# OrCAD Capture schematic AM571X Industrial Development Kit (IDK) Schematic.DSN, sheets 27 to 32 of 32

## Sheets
27 Pg16: Gbit Ethernet #0: size C
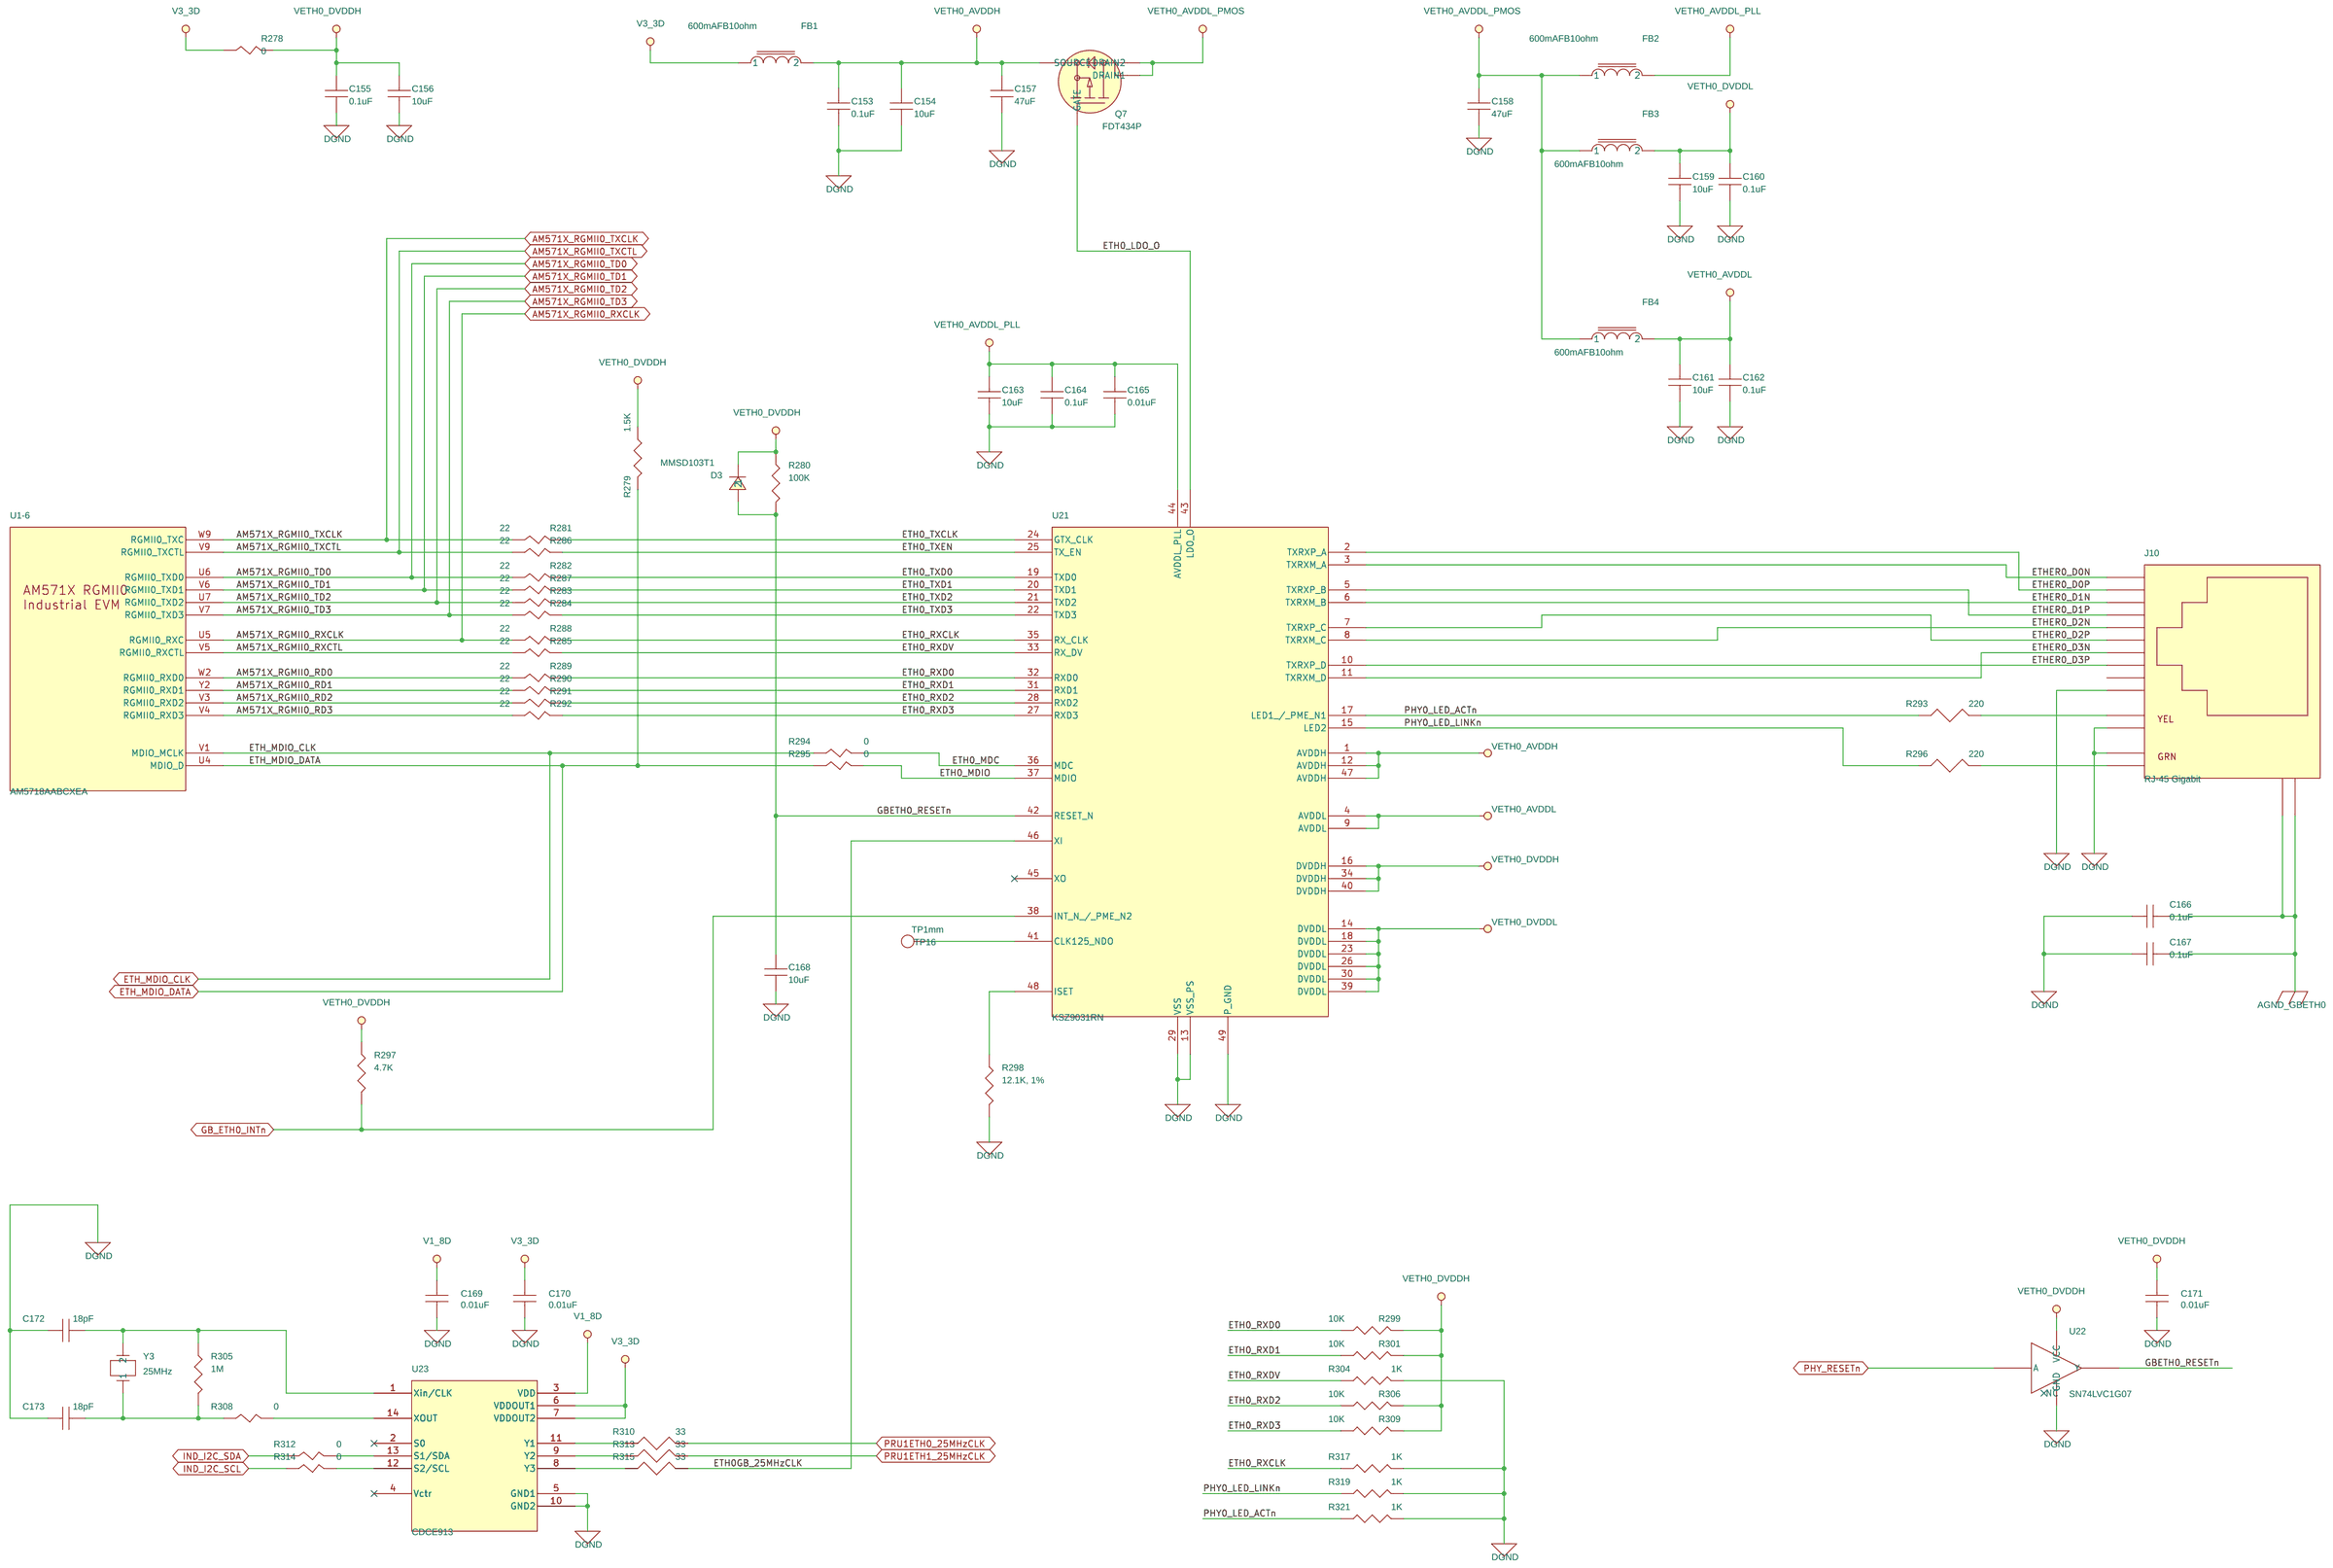
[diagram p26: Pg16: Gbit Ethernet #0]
28 Pg07: QSPI Flash Memory: size C
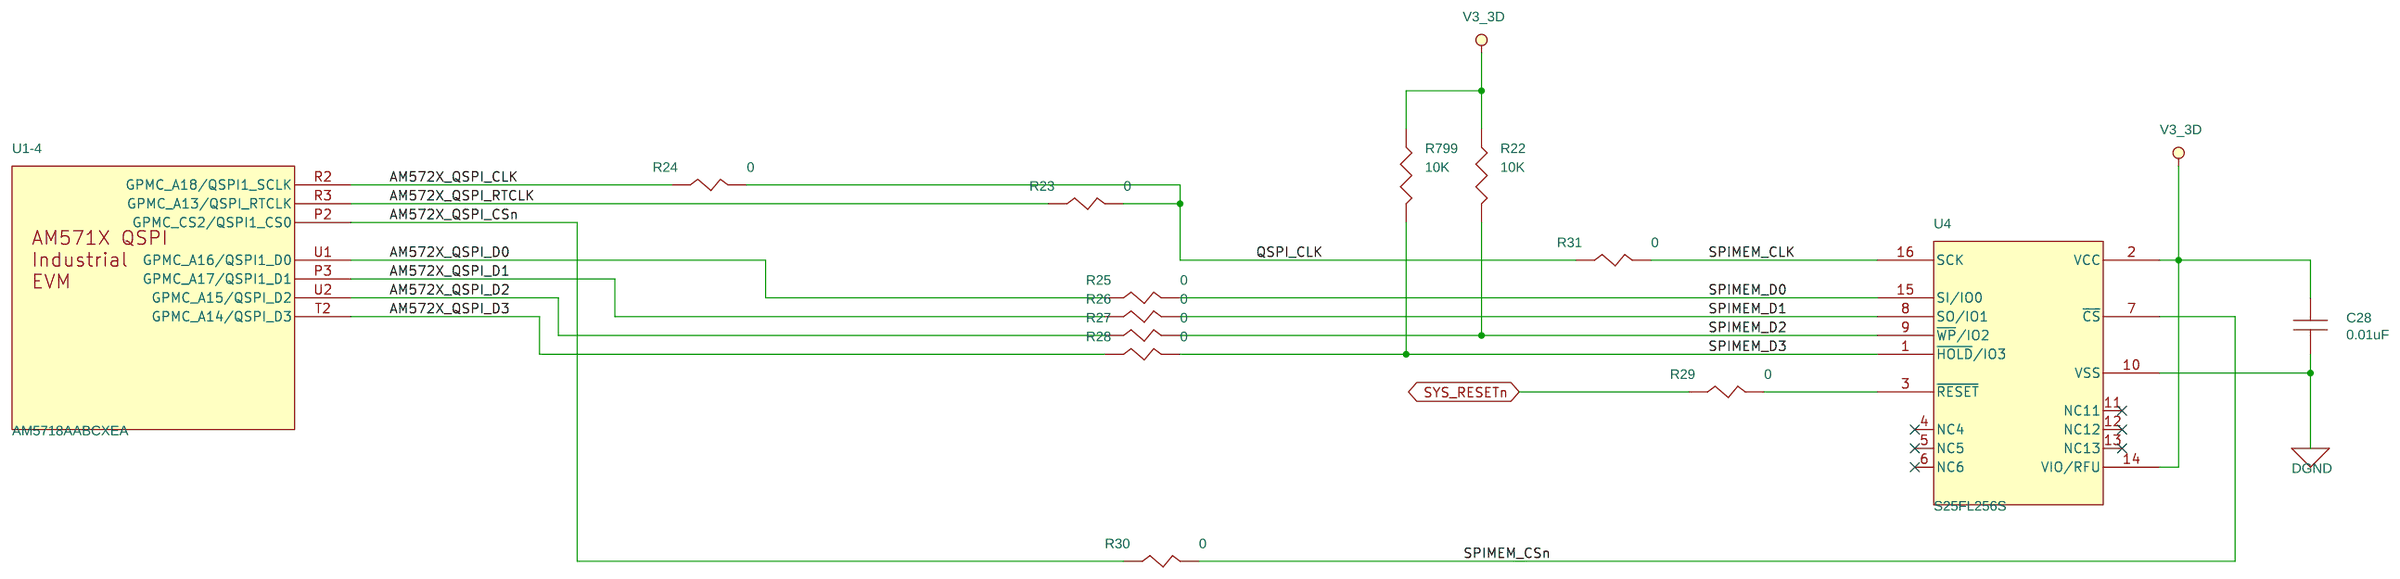
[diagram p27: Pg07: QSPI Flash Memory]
29 Pg32: Expansion Connector: size C
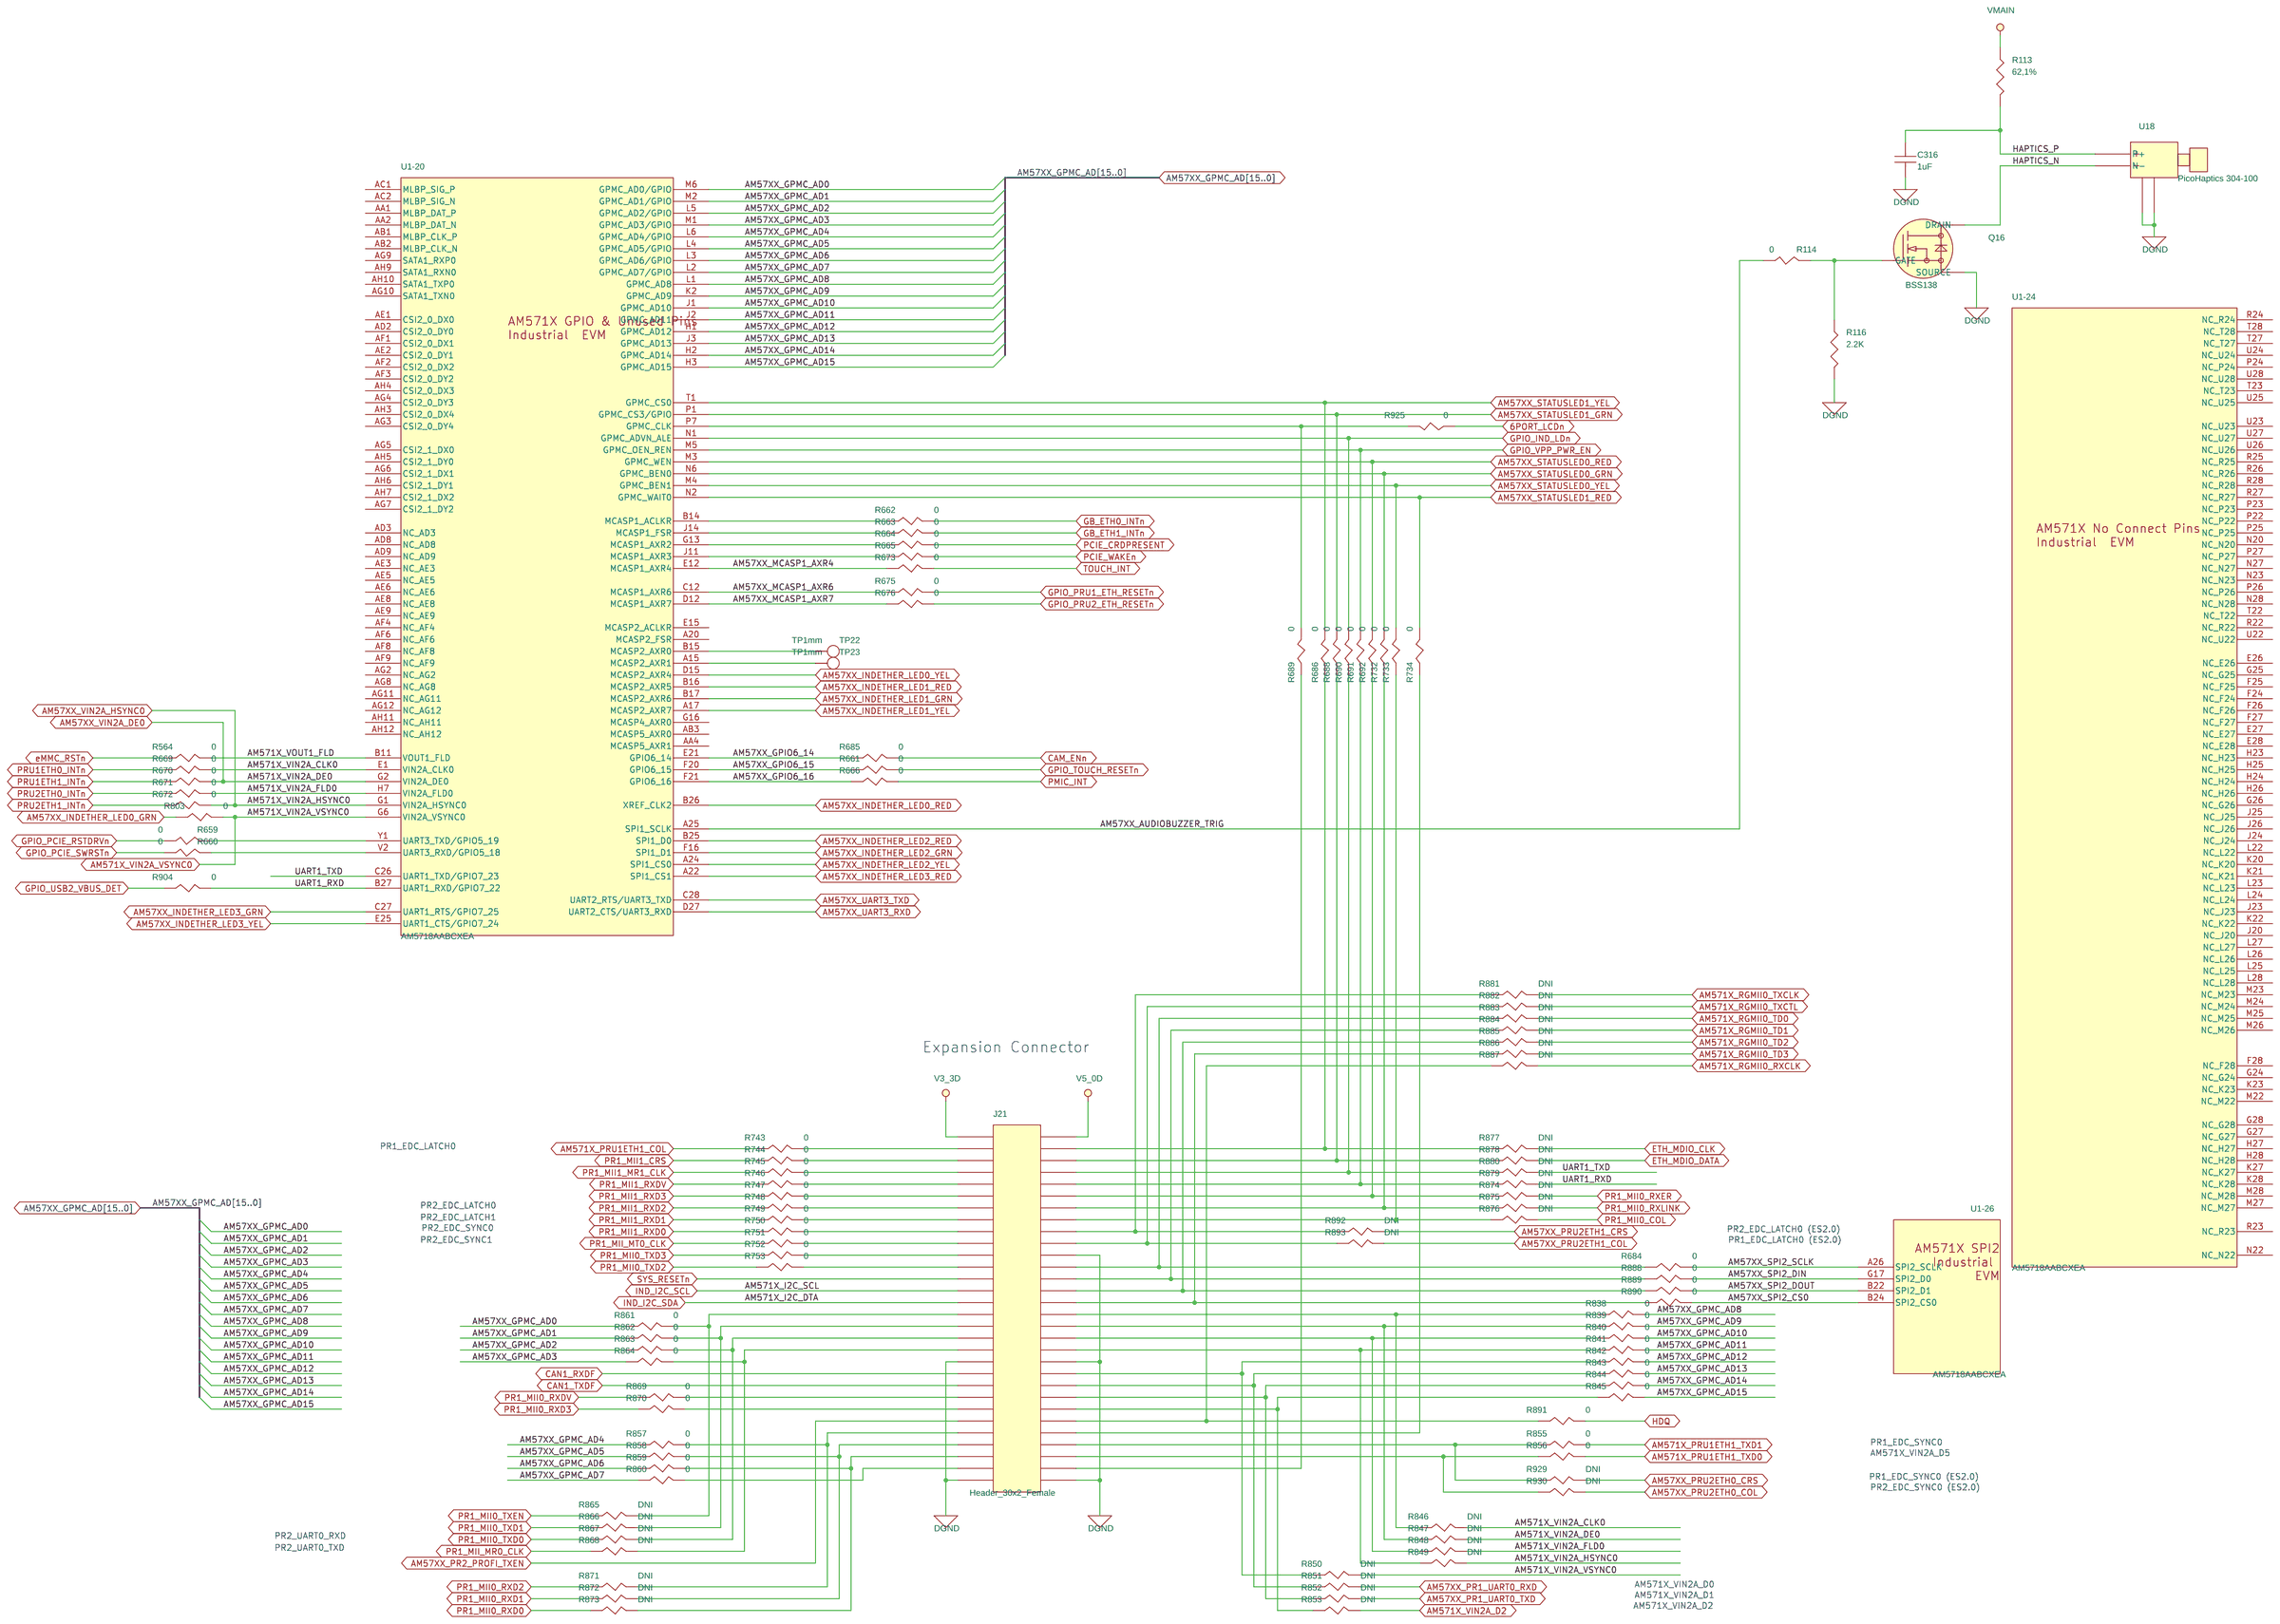
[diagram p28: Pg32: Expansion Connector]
30 Pg02: Processor subsystem: size C
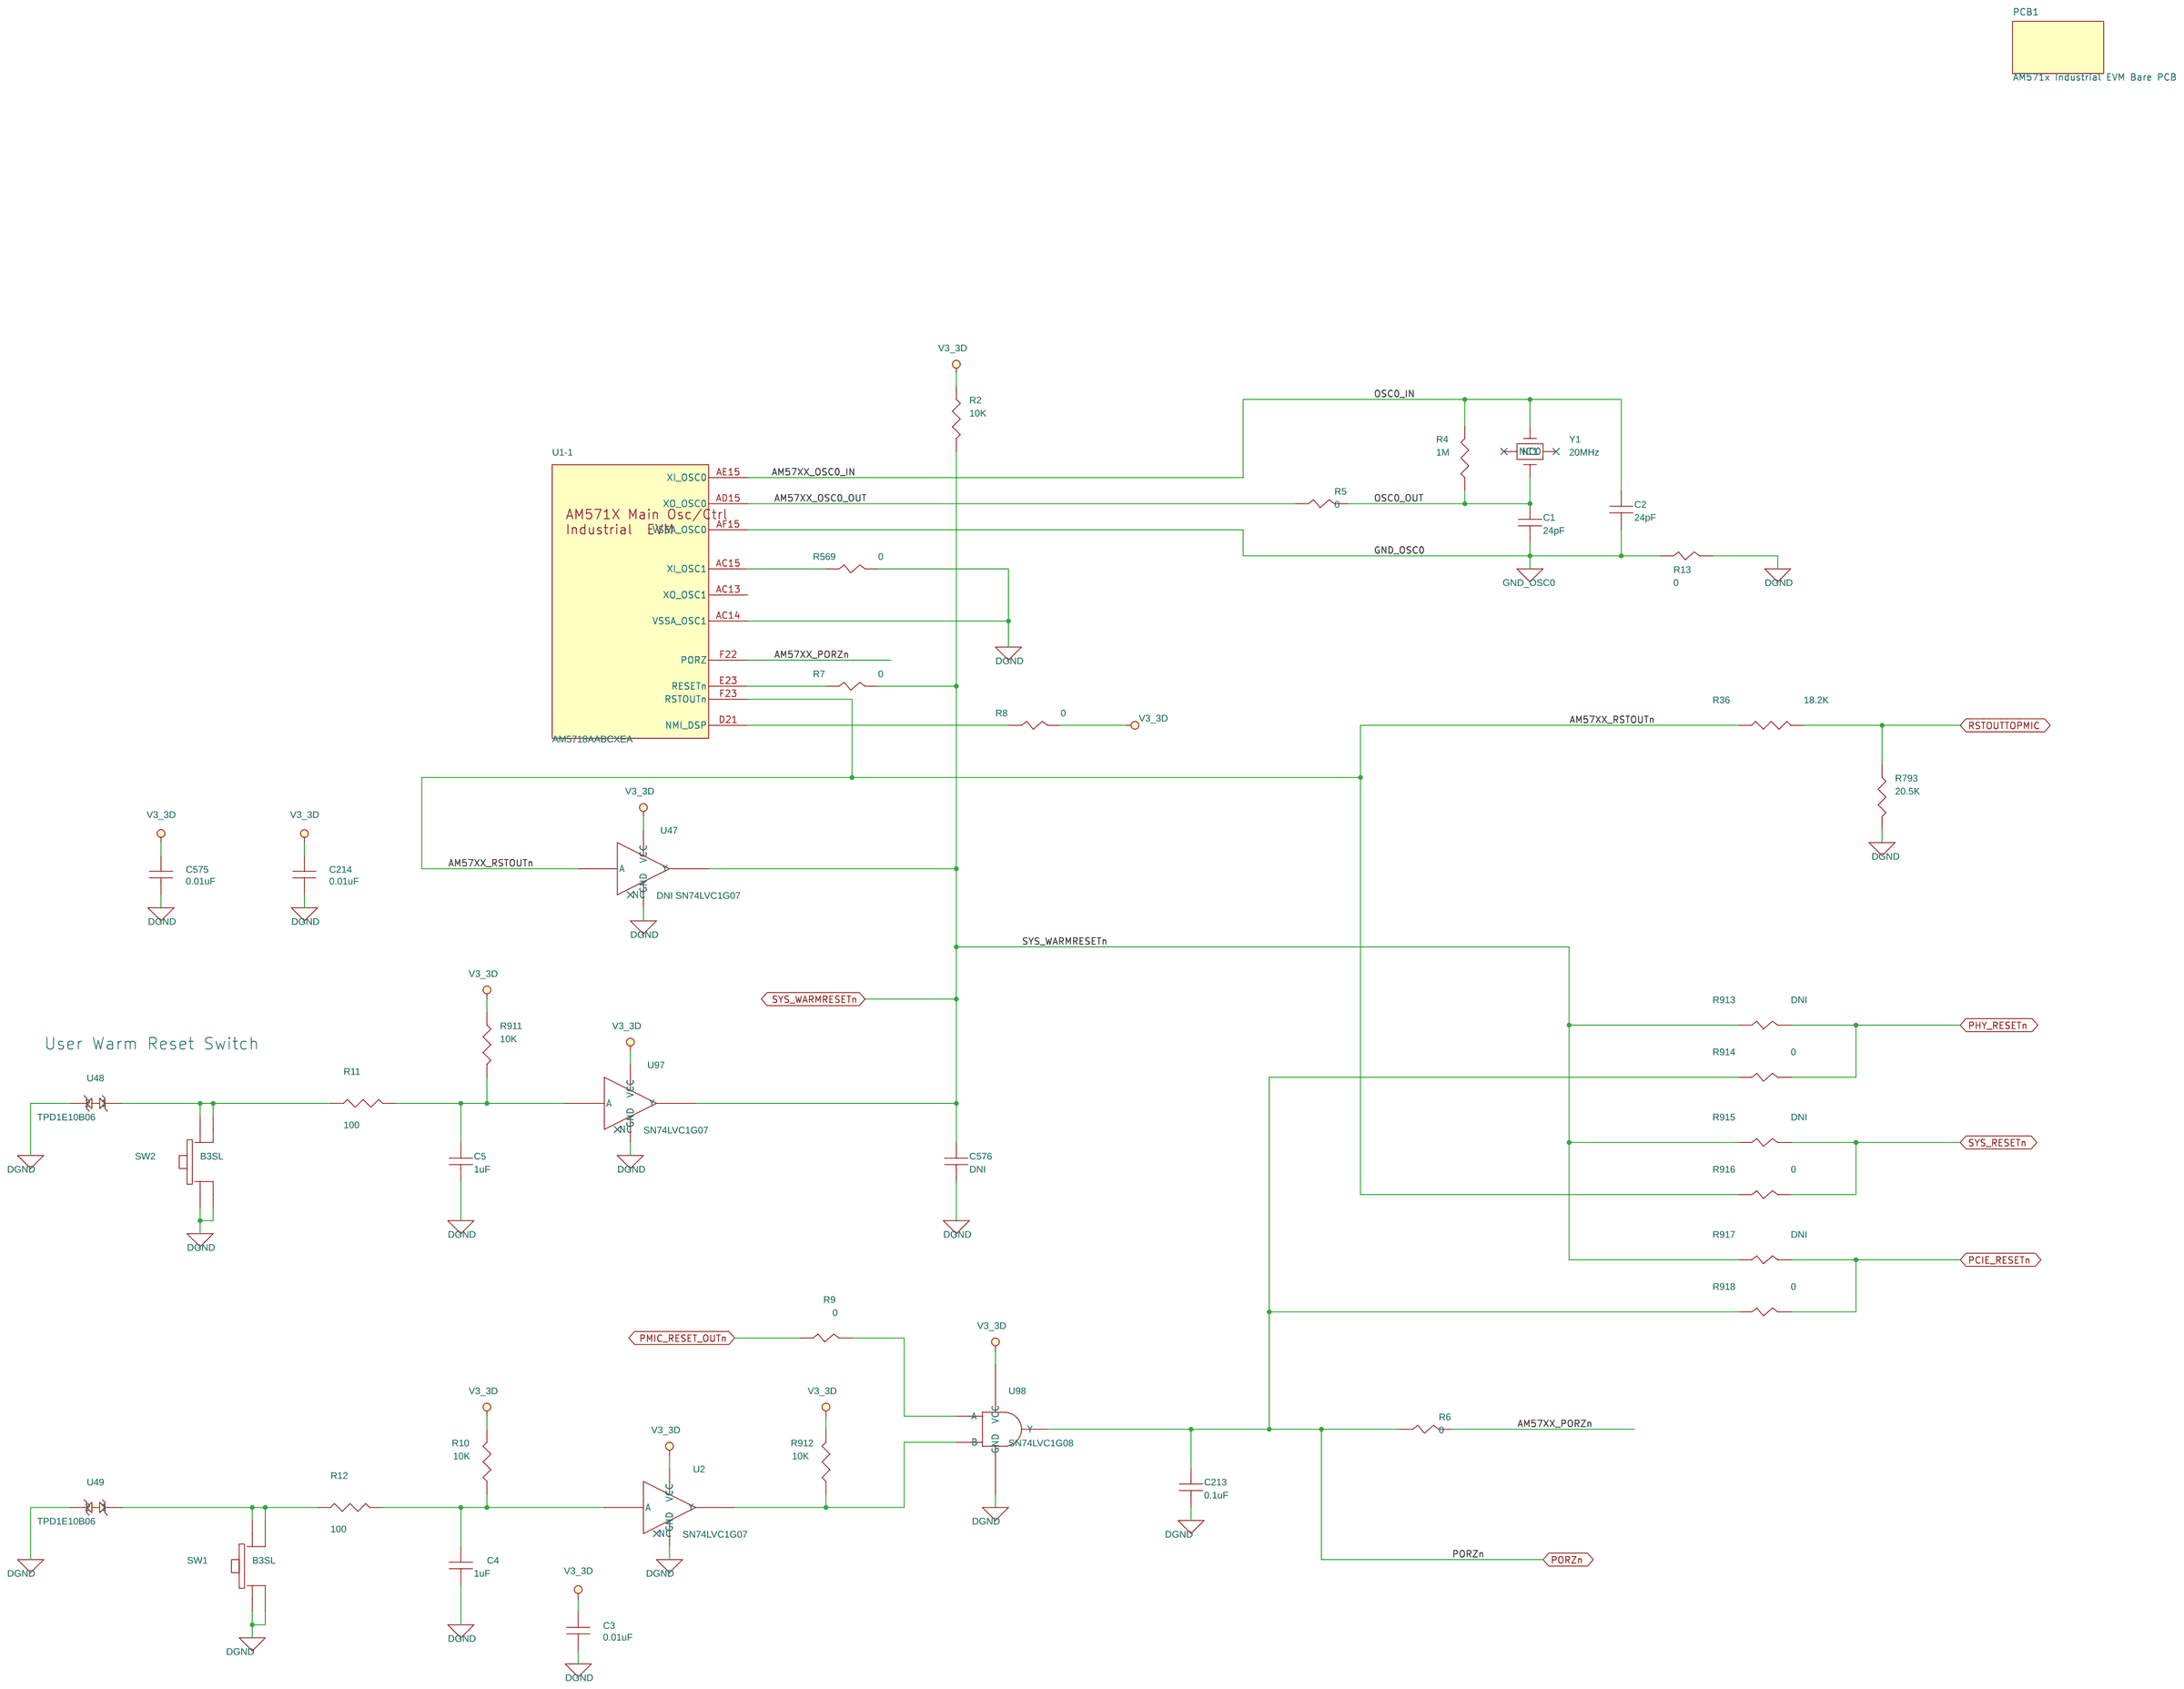
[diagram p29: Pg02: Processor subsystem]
31 Pg04: Processor Pwr Decoupling: size C
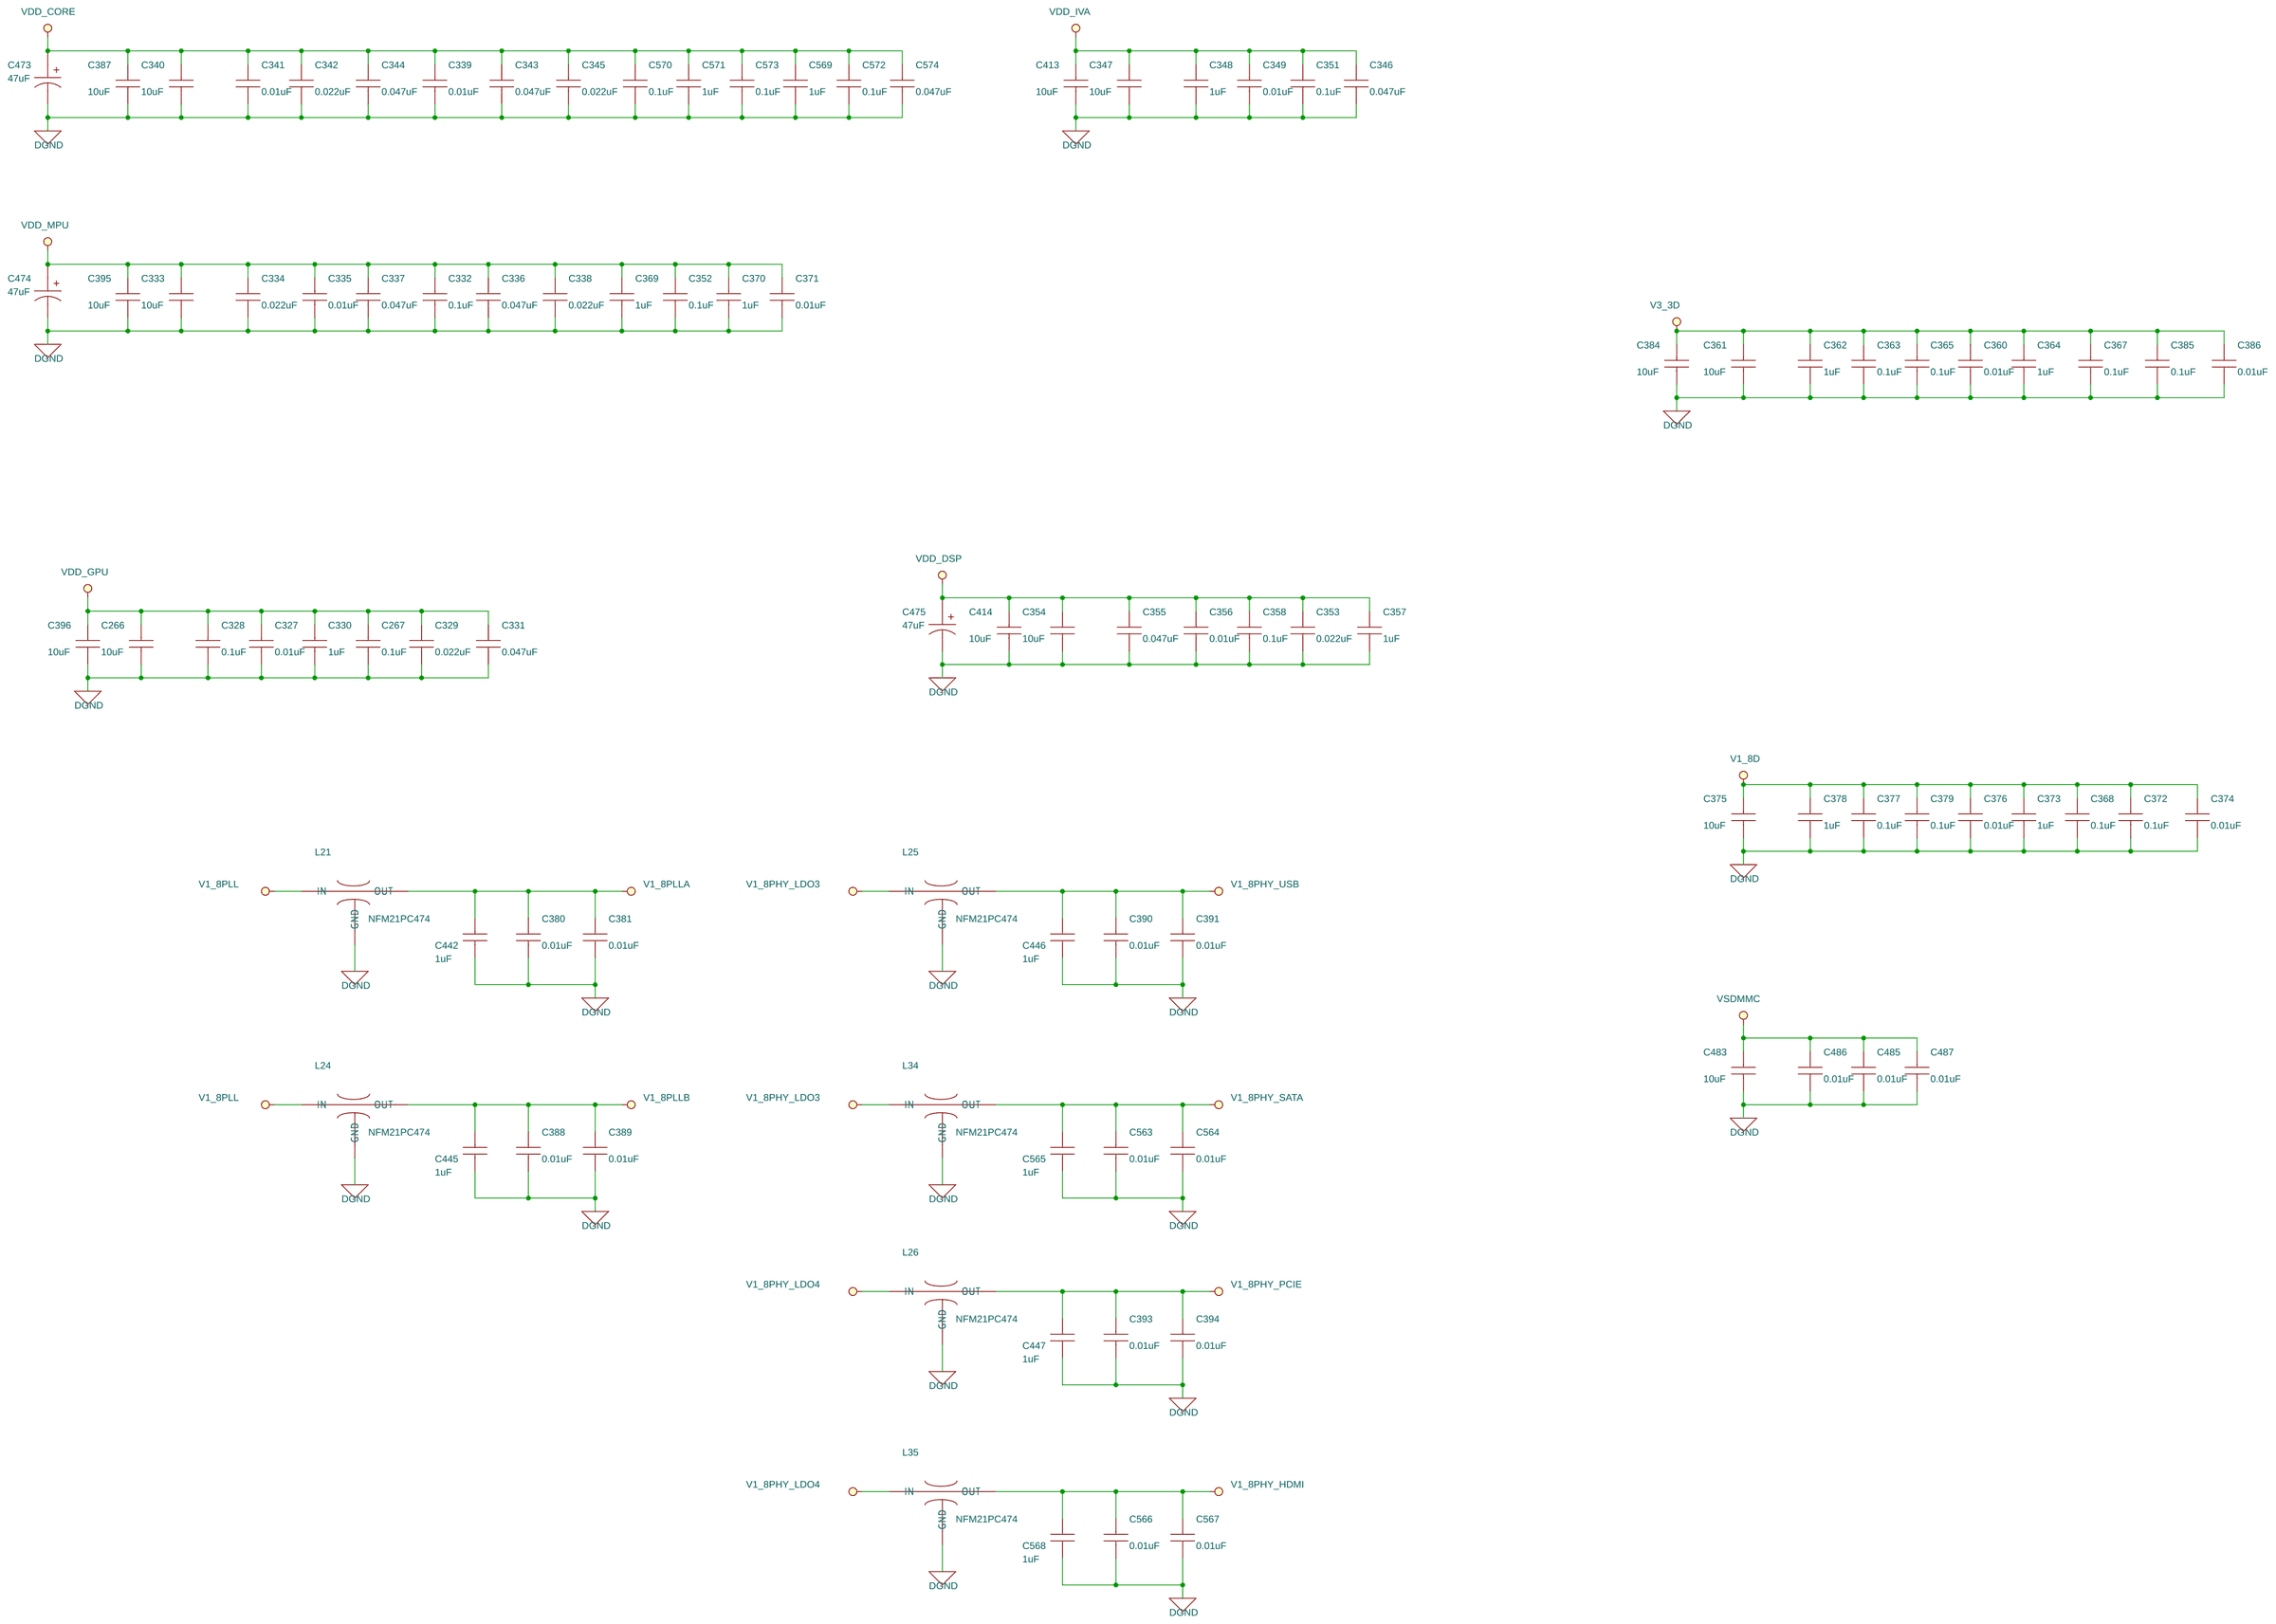
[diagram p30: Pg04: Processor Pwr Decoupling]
32 Pg14: Ind Ethrnt & Status LED's: size C
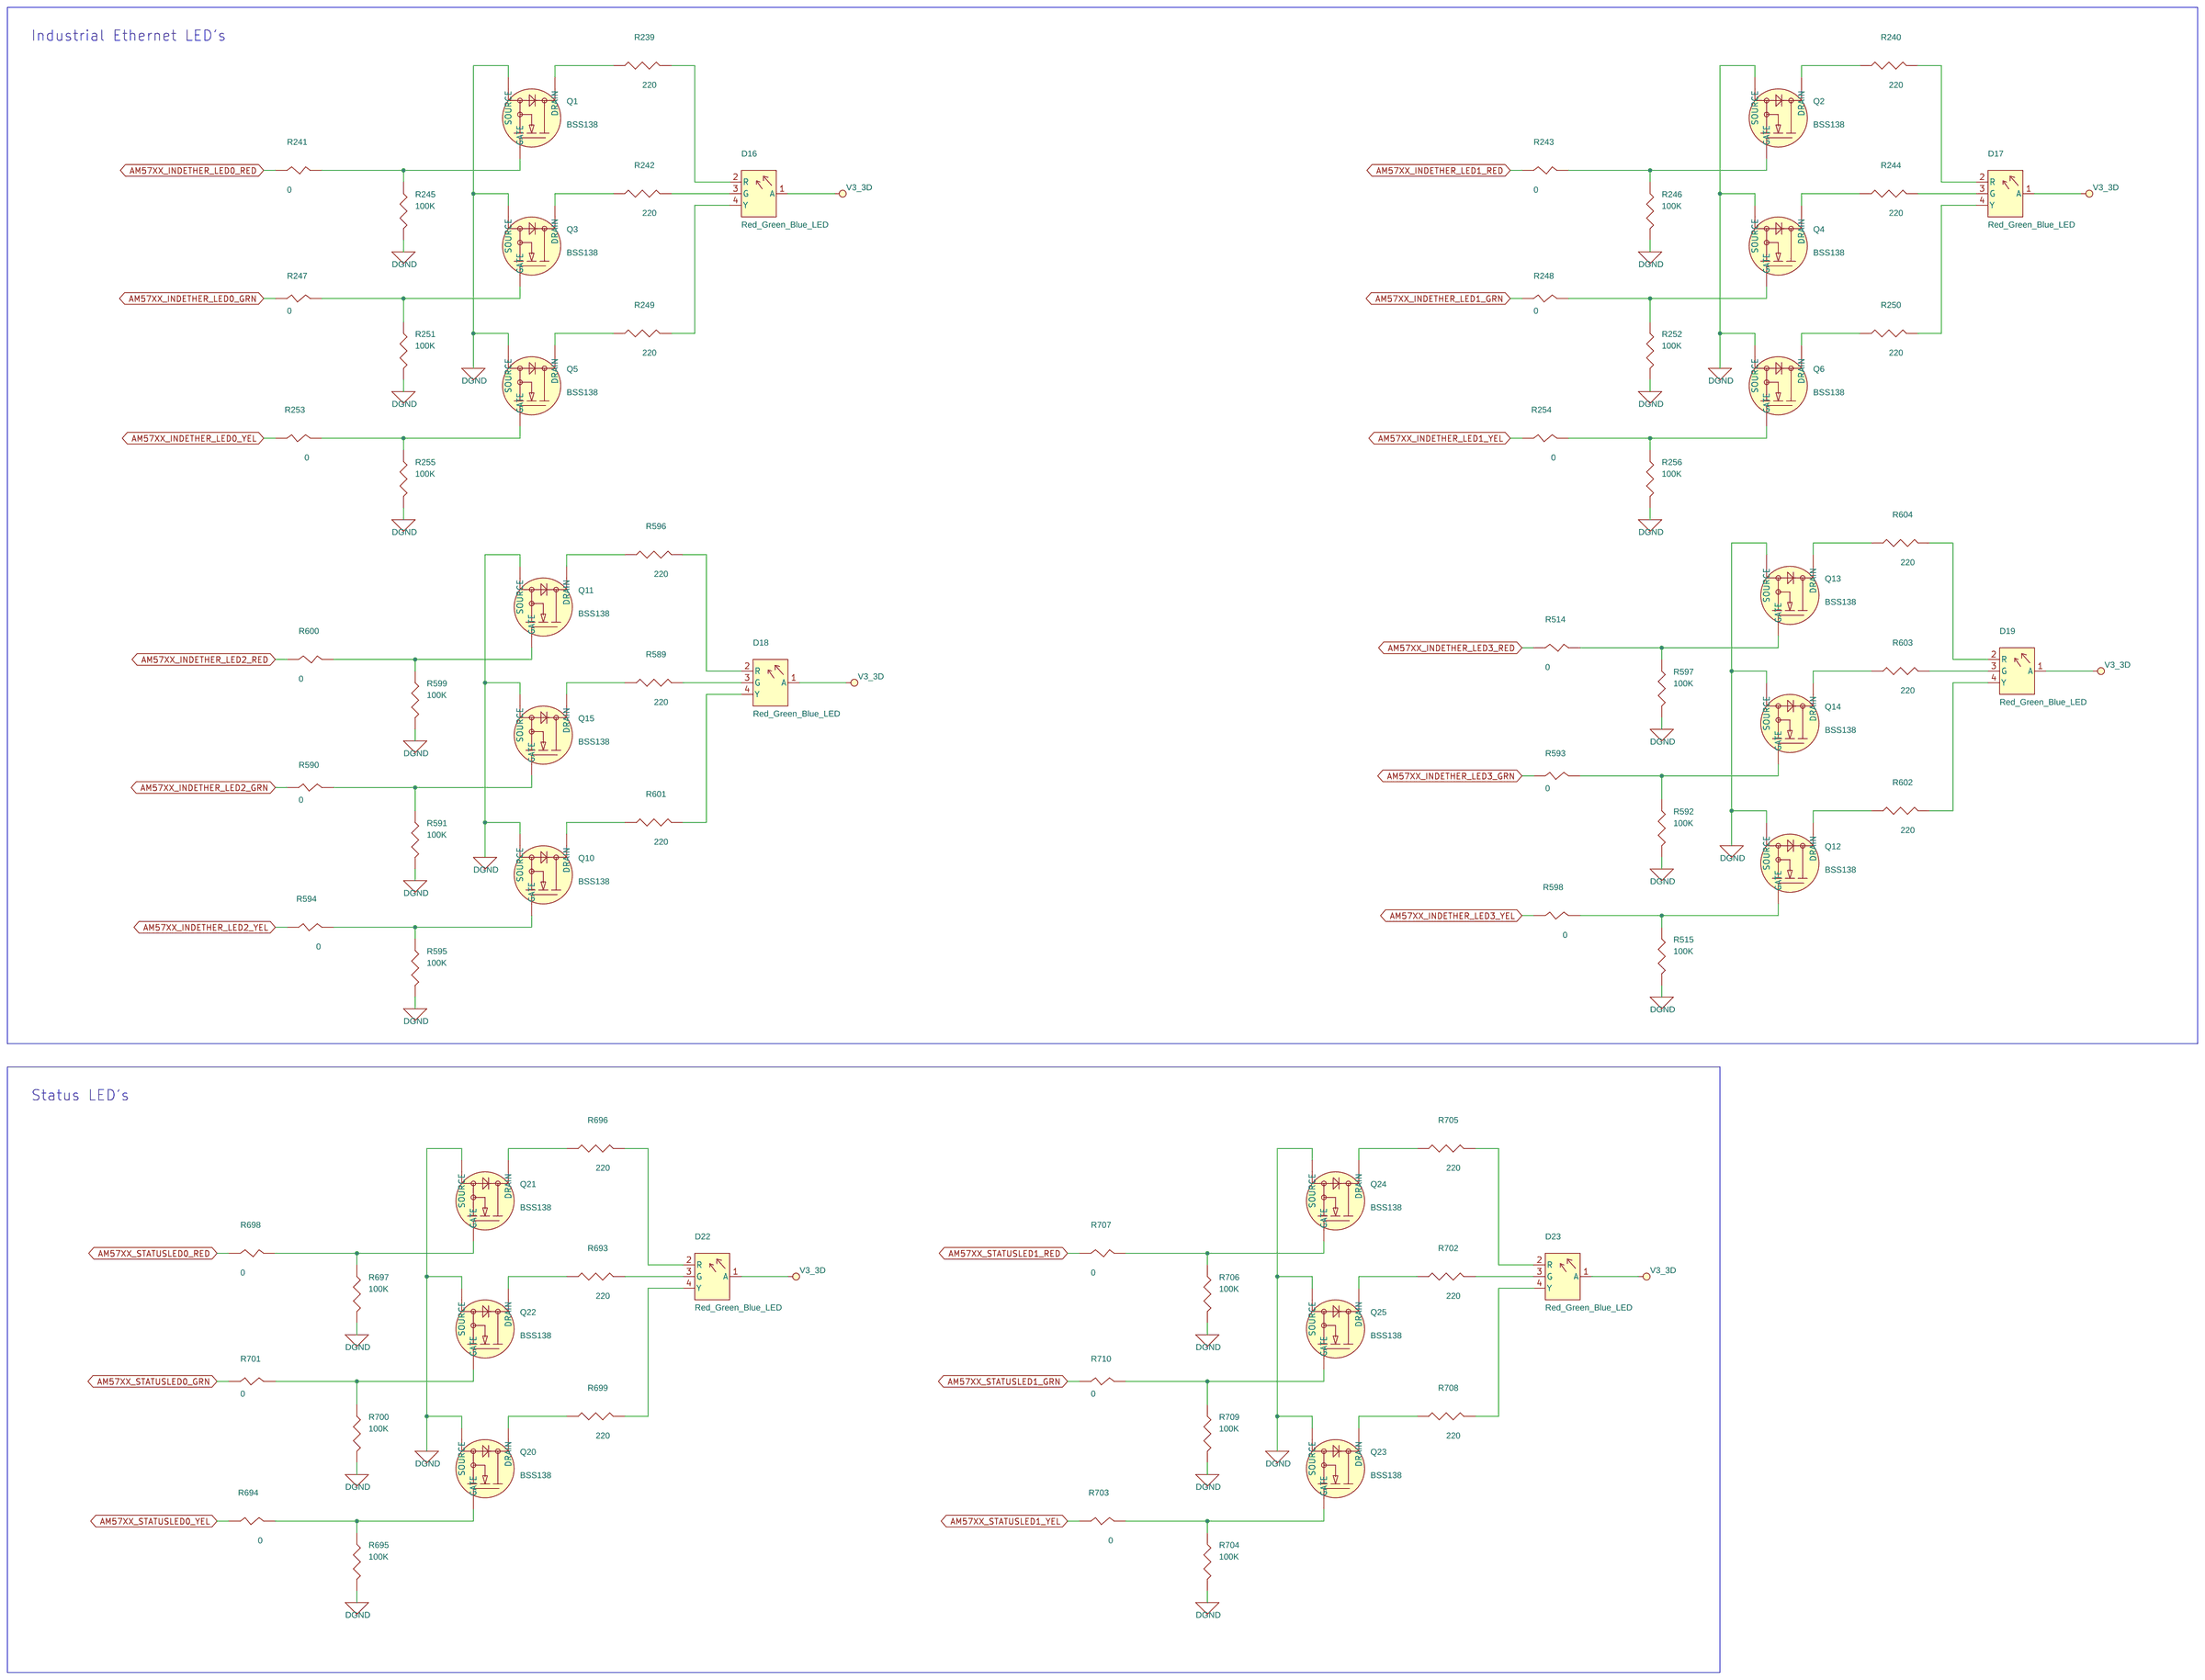
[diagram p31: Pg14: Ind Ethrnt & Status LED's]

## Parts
sheet Pg02: Processor subsystem
C1  24pF  [SM-7351-CAP-0402]
C2  24pF  [SM-7351-CAP-0402]
C3  0.01uF  [SM-7351-CAP-0402]
C4  1uF  [SM-7351-CAP-0402]
C5  1uF  [SM-7351-CAP-0402]
C213  0.1uF  [SM-7351-CAP-0402]
C214  0.01uF  [SM-7351-CAP-0402]
C575  0.01uF  [SM-7351-CAP-0402]
C576  DNI  [SM-7351-CAP-0402]
PCB1  AM571x Industrial EVM Bare PCB  [DNP]
R2  10K  [SM-7351-RES-0402]
R4  1M  [SM-7351-RES-0402]
R5  0  [SM-7351-RES-0402]
R6  0  [SM-7351-RES-0402]
R7  0  [SM-7351-RES-0402]
R8  0  [SM-7351-RES-0402]
R9  0  [SM-7351-RES-0402]
R10  10K  [SM-7351-RES-0402]
R11  100  [SM-7351-RES-0402]
R12  100  [SM-7351-RES-0402]
R13  0  [SM-7351-RES-0402]
R36  18.2K  [SM-7351-RES-0402]
R569  0  [SM-7351-RES-0402]
R793  20.5K  [SM-7351-RES-0402]
R911  10K  [SM-7351-RES-0402]
R912  10K  [SM-7351-RES-0402]
R913  DNI  [SM-7351-RES-0402]
R914  0  [SM-7351-RES-0402]
R915  DNI  [SM-7351-RES-0402]
R916  0  [SM-7351-RES-0402]
R917  DNI  [SM-7351-RES-0402]
R918  0  [SM-7351-RES-0402]
SW1  B3SL  [SW_B3SL-1022P]
SW2  B3SL  [SW_B3SL-1022P]
U2  SN74LVC1G07  [SC70-5-43M]
U47  DNI SN74LVC1G07  [SC70-5-43M]
U48  TPD1E10B06  [tpd1e10b06-2l]
U49  TPD1E10B06  [tpd1e10b06-2l]
U97  SN74LVC1G07  [SC70-5-43M]
U98  SN74LVC1G08  [sm-so-sc70-5]
Y1  20MHz  [XTAL2X3-30M]
sheet Pg04: Processor Pwr Decoupling
C266  10uF  [SM-7351-CAP-0805]
C267  0.1uF  [SM-7351-CAP-0402]
C327  0.01uF  [SM-7351-CAP-0402]
C328  0.1uF  [SM-7351-CAP-0402]
C329  0.022uF  [SM-7351-CAP-0402]
C330  1uF  [SM-7351-CAP-0402]
C331  0.047uF  [SM-7351-CAP-0402]
C332  0.1uF  [SM-7351-CAP-0402]
C333  10uF  [SM-7351-CAP-0805]
C334  0.022uF  [SM-7351-CAP-0402]
C335  0.01uF  [SM-7351-CAP-0402]
C336  0.047uF  [SM-7351-CAP-0402]
C337  0.047uF  [SM-7351-CAP-0402]
C338  0.022uF  [SM-7351-CAP-0402]
C339  0.01uF  [SM-7351-CAP-0402]
C340  10uF  [SM-7351-CAP-0805]
C341  0.01uF  [SM-7351-CAP-0402]
C342  0.022uF  [SM-7351-CAP-0402]
C343  0.047uF  [SM-7351-CAP-0402]
C344  0.047uF  [SM-7351-CAP-0402]
C345  0.022uF  [SM-7351-CAP-0402]
C346  0.047uF  [SM-7351-CAP-0402]
C347  10uF  [SM-7351-CAP-0805]
C348  1uF  [SM-7351-CAP-0402]
C349  0.01uF  [SM-7351-CAP-0402]
C351  0.1uF  [SM-7351-CAP-0402]
C352  0.1uF  [SM-7351-CAP-0402]
C353  0.022uF  [SM-7351-CAP-0402]
C354  10uF  [SM-7351-CAP-0805]
C355  0.047uF  [SM-7351-CAP-0402]
C356  0.01uF  [SM-7351-CAP-0402]
C357  1uF  [SM-7351-CAP-0402]
C358  0.1uF  [SM-7351-CAP-0402]
C360  0.01uF  [SM-7351-CAP-0402]
C361  10uF  [SM-7351-CAP-0805]
C362  1uF  [SM-7351-CAP-0402]
C363  0.1uF  [SM-7351-CAP-0402]
C364  1uF  [SM-7351-CAP-0402]
C365  0.1uF  [SM-7351-CAP-0402]
C367  0.1uF  [SM-7351-CAP-0402]
C368  0.1uF  [SM-7351-CAP-0402]
C369  1uF  [SM-7351-CAP-0402]
C370  1uF  [SM-7351-CAP-0402]
C371  0.01uF  [SM-7351-CAP-0402]
C372  0.1uF  [SM-7351-CAP-0402]
C373  1uF  [SM-7351-CAP-0402]
C374  0.01uF  [SM-7351-CAP-0402]
C375  10uF  [SM-7351-CAP-0805]
C376  0.01uF  [SM-7351-CAP-0402]
C377  0.1uF  [SM-7351-CAP-0402]
C378  1uF  [SM-7351-CAP-0402]
C379  0.1uF  [SM-7351-CAP-0402]
C380  0.01uF  [SM-7351-CAP-0402]
C381  0.01uF  [SM-7351-CAP-0402]
C384  10uF  [SM-7351-CAP-0805]
C385  0.1uF  [SM-7351-CAP-0402]
C386  0.01uF  [SM-7351-CAP-0402]
C387  10uF  [SM-7351-CAP-0805]
C388  0.01uF  [SM-7351-CAP-0402]
C389  0.01uF  [SM-7351-CAP-0402]
C390  0.01uF  [SM-7351-CAP-0402]
C391  0.01uF  [SM-7351-CAP-0402]
C393  0.01uF  [SM-7351-CAP-0402]
C394  0.01uF  [SM-7351-CAP-0402]
C395  10uF  [SM-7351-CAP-0805]
C396  10uF  [SM-7351-CAP-0805]
C413  10uF  [SM-7351-CAP-0805]
C414  10uF  [SM-7351-CAP-0805]
C442  1uF  [SM-7351-CAP-0402]
C445  1uF  [SM-7351-CAP-0402]
C446  1uF  [SM-7351-CAP-0402]
C447  1uF  [SM-7351-CAP-0402]
C473  47uF  [7343]
C474  47uF  [7343]
C475  47uF  [7343]
C483  10uF  [SM-7351-CAP-0805]
C485  0.01uF  [SM-7351-CAP-0402]
C486  0.01uF  [SM-7351-CAP-0402]
C487  0.01uF  [SM-7351-CAP-0402]
C563  0.01uF  [SM-7351-CAP-0402]
C564  0.01uF  [SM-7351-CAP-0402]
C565  1uF  [SM-7351-CAP-0402]
C566  0.01uF  [SM-7351-CAP-0402]
C567  0.01uF  [SM-7351-CAP-0402]
C568  1uF  [SM-7351-CAP-0402]
C569  1uF  [SM-7351-CAP-0402]
C570  0.1uF  [SM-7351-CAP-0402]
C571  1uF  [SM-7351-CAP-0402]
C572  0.1uF  [SM-7351-CAP-0402]
C573  0.1uF  [SM-7351-CAP-0402]
C574  0.047uF  [SM-7351-CAP-0402]
L21  NFM21PC474  [FILT-NFM21PC]
L24  NFM21PC474  [FILT-NFM21PC]
L25  NFM21PC474  [FILT-NFM21PC]
L26  NFM21PC474  [FILT-NFM21PC]
L34  NFM21PC474  [FILT-NFM21PC]
L35  NFM21PC474  [FILT-NFM21PC]
sheet Pg07: QSPI Flash Memory
C28  0.01uF  [SM-7351-CAP-0402]
R22  10K  [SM-7351-RES-0402]
R23  0  [SM-7351-RES-0402]
R24  0  [SM-7351-RES-0402]
R25  0  [SM-7351-RES-0402]
R26  0  [SM-7351-RES-0402]
R27  0  [SM-7351-RES-0402]
R28  0  [SM-7351-RES-0402]
R29  0  [SM-7351-RES-0402]
R30  0  [SM-7351-RES-0402]
R31  0  [SM-7351-RES-0402]
R799  10K  [SM-7351-RES-0402]
U4  S25FL256S  [soic_16pin_dw]
sheet Pg14: Ind Ethrnt & Status LED's
D16  Red_Green_Blue_LED  [LED-SM1210]
D17  Red_Green_Blue_LED  [LED-SM1210]
D18  Red_Green_Blue_LED  [LED-SM1210]
D19  Red_Green_Blue_LED  [LED-SM1210]
D22  Red_Green_Blue_LED  [LED-SM1210]
D23  Red_Green_Blue_LED  [LED-SM1210]
Q1  BSS138  [SOT23-3]
Q2  BSS138  [SOT23-3]
Q3  BSS138  [SOT23-3]
Q4  BSS138  [SOT23-3]
Q5  BSS138  [SOT23-3]
Q6  BSS138  [SOT23-3]
Q10  BSS138  [SOT23-3]
Q11  BSS138  [SOT23-3]
Q12  BSS138  [SOT23-3]
Q13  BSS138  [SOT23-3]
Q14  BSS138  [SOT23-3]
Q15  BSS138  [SOT23-3]
Q20  BSS138  [SOT23-3]
Q21  BSS138  [SOT23-3]
Q22  BSS138  [SOT23-3]
Q23  BSS138  [SOT23-3]
Q24  BSS138  [SOT23-3]
Q25  BSS138  [SOT23-3]
R239  220  [SM-7351-RES-0402]
R240  220  [SM-7351-RES-0402]
R241  0  [SM-7351-RES-0402]
R242  220  [SM-7351-RES-0402]
R243  0  [SM-7351-RES-0402]
R244  220  [SM-7351-RES-0402]
R245  100K  [SM-7351-RES-0402]
R246  100K  [SM-7351-RES-0402]
R247  0  [SM-7351-RES-0402]
R248  0  [SM-7351-RES-0402]
R249  220  [SM-7351-RES-0402]
R250  220  [SM-7351-RES-0402]
R251  100K  [SM-7351-RES-0402]
R252  100K  [SM-7351-RES-0402]
R253  0  [SM-7351-RES-0402]
R254  0  [SM-7351-RES-0402]
R255  100K  [SM-7351-RES-0402]
R256  100K  [SM-7351-RES-0402]
R514  0  [SM-7351-RES-0402]
R515  100K  [SM-7351-RES-0402]
R589  220  [SM-7351-RES-0402]
R590  0  [SM-7351-RES-0402]
R591  100K  [SM-7351-RES-0402]
R592  100K  [SM-7351-RES-0402]
R593  0  [SM-7351-RES-0402]
R594  0  [SM-7351-RES-0402]
R595  100K  [SM-7351-RES-0402]
R596  220  [SM-7351-RES-0402]
R597  100K  [SM-7351-RES-0402]
R598  0  [SM-7351-RES-0402]
R599  100K  [SM-7351-RES-0402]
R600  0  [SM-7351-RES-0402]
R601  220  [SM-7351-RES-0402]
R602  220  [SM-7351-RES-0402]
R603  220  [SM-7351-RES-0402]
R604  220  [SM-7351-RES-0402]
R693  220  [SM-7351-RES-0402]
R694  0  [SM-7351-RES-0402]
R695  100K  [SM-7351-RES-0402]
R696  220  [SM-7351-RES-0402]
R697  100K  [SM-7351-RES-0402]
R698  0  [SM-7351-RES-0402]
R699  220  [SM-7351-RES-0402]
R700  100K  [SM-7351-RES-0402]
R701  0  [SM-7351-RES-0402]
R702  220  [SM-7351-RES-0402]
R703  0  [SM-7351-RES-0402]
R704  100K  [SM-7351-RES-0402]
R705  220  [SM-7351-RES-0402]
R706  100K  [SM-7351-RES-0402]
R707  0  [SM-7351-RES-0402]
R708  220  [SM-7351-RES-0402]
R709  100K  [SM-7351-RES-0402]
R710  0  [SM-7351-RES-0402]
sheet Pg16: Gbit Ethernet #0
C153  0.1uF  [SM-7351-CAP-0402]
C154  10uF  [SM-7351-CAP-0805]
C155  0.1uF  [SM-7351-CAP-0402]
C156  10uF  [SM-7351-CAP-0805]
C157  47uF  [SM-7351-CAP-1206]
C158  47uF  [SM-7351-CAP-1206]
C159  10uF  [SM-7351-CAP-0805]
C160  0.1uF  [SM-7351-CAP-0402]
C161  10uF  [SM-7351-CAP-0805]
C162  0.1uF  [SM-7351-CAP-0402]
C163  10uF  [SM-7351-CAP-0805]
C164  0.1uF  [SM-7351-CAP-0402]
C165  0.01uF  [SM-7351-CAP-0402]
C166  0.1uF  [SM-7351-CAP-0402]
C167  0.1uF  [SM-7351-CAP-0402]
C168  10uF  [SM-7351-CAP-0805]
C169  0.01uF  [SM-7351-CAP-0402]
C170  0.01uF  [SM-7351-CAP-0402]
C171  0.01uF  [SM-7351-CAP-0402]
C172  18pF  [SM-7351-CAP-0402]
C173  18pF  [SM-7351-CAP-0402]
D3  MMSD103T1  [sod-123]
FB1  600mAFB10ohm  [HF70ACB201209]
FB2  600mAFB10ohm  [HF70ACB201209]
FB3  600mAFB10ohm  [HF70ACB201209]
FB4  600mAFB10ohm  [HF70ACB201209]
J10  RJ-45 Gigabit  [CNRJ45-1X1WLED-598M]
Q7  FDT434P  [SOT223-4]
R278  0  [SM-7351-RES-0603]
R279  1.5K  [SM-7351-RES-0402]
R280  100K  [SM-7351-RES-0402]
R281  22  [SM-7351-RES-0402]
R282  22  [SM-7351-RES-0402]
R283  22  [SM-7351-RES-0402]
R284  22  [SM-7351-RES-0402]
R285  22  [SM-7351-RES-0402]
R286  22  [SM-7351-RES-0402]
R287  22  [SM-7351-RES-0402]
R288  22  [SM-7351-RES-0402]
R289  22  [SM-7351-RES-0402]
R290  22  [SM-7351-RES-0402]
R291  22  [SM-7351-RES-0402]
R292  22  [SM-7351-RES-0402]
R293  220  [SM-7351-RES-0402]
R294  0  [SM-7351-RES-0402]
R295  0  [SM-7351-RES-0402]
R296  220  [SM-7351-RES-0402]
R297  4.7K  [SM-7351-RES-0402]
R298  12.1K, 1%  [SM-7351-RES-0402]
R299  10K  [SM-7351-RES-0402]
R301  10K  [SM-7351-RES-0402]
R304  1K  [SM-7351-RES-0402]
R305  1M  [SM-7351-RES-0402]
R306  10K  [SM-7351-RES-0402]
R308  0  [SM-7351-RES-0402]
R309  10K  [SM-7351-RES-0402]
R310  33  [SM-7351-RES-0402]
R312  0  [SM-7351-RES-0402]
R313  33  [SM-7351-RES-0402]
R314  0  [SM-7351-RES-0402]
R315  33  [SM-7351-RES-0402]
R317  1K  [SM-7351-RES-0402]
R319  1K  [SM-7351-RES-0402]
R321  1K  [SM-7351-RES-0402]
TP16  TP1mm  [tp_smd1mmcircle]
U21  KSZ9031RN  [qfn7x7-48]
U22  SN74LVC1G07  [SC70-5-43M]
U23  CDCE913  [TSSOP5X4-14-47M]
Y3  25MHz  [SM_OSC_ABM3]
sheet Pg32: Expansion Connector
C316  1uF  [SM-7351-CAP-0603]
J21  Header_30x2_Female  [HDR2X30-2mm-177m]
Q16  BSS138  [SOT23-3]
R113  62,1%  [sm-7351-res-0402]
R114  0  [SM-7351-RES-0402]
R116  2.2K  [sm-7351-res-0402]
R564  0  [SM-7351-RES-0402]
R659  0  [SM-7351-RES-0402]
R660  0  [SM-7351-RES-0402]
R661  0  [SM-7351-RES-0402]
R662  0  [SM-7351-RES-0402]
R663  0  [SM-7351-RES-0402]
R664  0  [SM-7351-RES-0402]
R665  0  [SM-7351-RES-0402]
R666  0  [SM-7351-RES-0402]
R669  0  [SM-7351-RES-0402]
R670  0  [SM-7351-RES-0402]
R671  0  [SM-7351-RES-0402]
R672  0  [SM-7351-RES-0402]
R673  0  [SM-7351-RES-0402]
R675  0  [SM-7351-RES-0402]
R676  0  [SM-7351-RES-0402]
R684  0  [SM-7351-RES-0402]
R685  0  [SM-7351-RES-0402]
R686  0  [SM-7351-RES-0402]
R688  0  [SM-7351-RES-0402]
R689  0  [SM-7351-RES-0402]
R690  0  [SM-7351-RES-0402]
R691  0  [SM-7351-RES-0402]
R692  0  [SM-7351-RES-0402]
R732  0  [SM-7351-RES-0402]
R733  0  [SM-7351-RES-0402]
R734  0  [SM-7351-RES-0402]
R743  0  [SM-7351-RES-0402]
R744  0  [SM-7351-RES-0402]
R745  0  [SM-7351-RES-0402]
R746  0  [SM-7351-RES-0402]
R747  0  [SM-7351-RES-0402]
R748  0  [SM-7351-RES-0402]
R749  0  [SM-7351-RES-0402]
R750  0  [SM-7351-RES-0402]
R751  0  [SM-7351-RES-0402]
R752  0  [SM-7351-RES-0402]
R753  0  [SM-7351-RES-0402]
R803  0  [SM-7351-RES-0402]
R838  0  [SM-7351-RES-0402]
R839  0  [SM-7351-RES-0402]
R840  0  [SM-7351-RES-0402]
R841  0  [SM-7351-RES-0402]
R842  0  [SM-7351-RES-0402]
R843  0  [SM-7351-RES-0402]
R844  0  [SM-7351-RES-0402]
R845  0  [SM-7351-RES-0402]
R846  DNI  [SM-7351-RES-0402]
R847  DNI  [SM-7351-RES-0402]
R848  DNI  [SM-7351-RES-0402]
R849  DNI  [SM-7351-RES-0402]
R850  DNI  [SM-7351-RES-0402]
R851  DNI  [SM-7351-RES-0402]
R852  DNI  [SM-7351-RES-0402]
R853  DNI  [SM-7351-RES-0402]
R855  0  [SM-7351-RES-0402]
R856  0  [SM-7351-RES-0402]
R857  0  [SM-7351-RES-0402]
R858  0  [SM-7351-RES-0402]
R859  0  [SM-7351-RES-0402]
R860  0  [SM-7351-RES-0402]
R861  0  [SM-7351-RES-0402]
R862  0  [SM-7351-RES-0402]
R863  0  [SM-7351-RES-0402]
R864  0  [SM-7351-RES-0402]
R865  DNI  [SM-7351-RES-0402]
R866  DNI  [SM-7351-RES-0402]
R867  DNI  [SM-7351-RES-0402]
R868  DNI  [SM-7351-RES-0402]
R869  0  [SM-7351-RES-0402]
R870  0  [SM-7351-RES-0402]
R871  DNI  [SM-7351-RES-0402]
R872  DNI  [SM-7351-RES-0402]
R873  DNI  [SM-7351-RES-0402]
R874  DNI  [SM-7351-RES-0402]
R875  DNI  [SM-7351-RES-0402]
R876  DNI  [SM-7351-RES-0402]
R877  DNI  [SM-7351-RES-0402]
R878  DNI  [SM-7351-RES-0402]
R879  DNI  [SM-7351-RES-0402]
R880  DNI  [SM-7351-RES-0402]
R881  DNI  [SM-7351-RES-0402]
R882  DNI  [SM-7351-RES-0402]
R883  DNI  [SM-7351-RES-0402]
R884  DNI  [SM-7351-RES-0402]
R885  DNI  [SM-7351-RES-0402]
R886  DNI  [SM-7351-RES-0402]
R887  DNI  [SM-7351-RES-0402]
R888  0  [SM-7351-RES-0402]
R889  0  [SM-7351-RES-0402]
R890  0  [SM-7351-RES-0402]
R891  0  [SM-7351-RES-0402]
R892  DNI  [SM-7351-RES-0402]
R893  DNI  [SM-7351-RES-0402]
R904  0  [SM-7351-RES-0402]
R925  0  [SM-7351-RES-0402]
R929  DNI  [SM-7351-RES-0402]
R930  DNI  [SM-7351-RES-0402]
TP22  TP1mm  [tp_smd1mmcircle]
TP23  TP1mm  [tp_smd1mmcircle]
U1  AM5718AABCXEA  [BGA23X23-760-117M]  (sections -1,-10,-11,-12,-13,-14,-15,-16,-17,-18,-19,-2,-20,-21,-22,-23,-24,-25,-26,-27,-3,-4,-5,-6,-7,-8,-9)
U18  PicoHaptics 304-100  [pico_304-100]

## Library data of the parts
C1 C2 = 1C_24pFCapacitor50V5%SMD0402
C3 C28 C165 C169-C171 C214 C327 C335 C339 C341 C349 C356 C360 C371 C374 C376 C380 C381 C386 C388-C391 C393 C394 C485-C487 C563 C564 C566 C567 C575 = 1C_0.01uFCapacitor16V10%0402
C4 C5 C576 = 1C_1uFCapacitor10V10%0402
C213 = 1C_0.1uFCapacitor16V10%0402: PN: C0402C104K4RACT
PCB1 = 3M_AM571xIDKEVMBarePCBv1_2
R2 R10 R22 R299 R301 R306 R309 R799 R911 R912 = 1R_10KOhmResistor1_16W0402
R4 R305 = 1MOhmResistor1_16W0402
R5-R9 R13 R23-R31 R114 R241 R243 R247 R248 R253 R254 R294 R295 R308 R312 R314 R514 R564 R569 R590 R593 R594 R598 R600 R659-R666 R669-R673 R675 R676 R684-R686 R688-R692 R694 R698 R701 R703 R707 R710 R732-R734 R743-R753 R803 R838-R853 R855-R893 R904 R913-R918 R925 R929 R930 = 1R_ZeroOhmResistor1_16W0402
R11 R12 = 1R_100ohm1_16W1%SMD0402
R36 = 1R_18.2Kohm1_16W1%smd0402
R793 = 1R_20.5Kohm1_16W1%smd0402
SW1 SW2 = 2W_Switch_Pushbuttonsmd
U2 U22 U47 U97 = 1A_SN74LVC1G07
U48 = 1A_TPD1E10B06_0_1
U49 = 1A_TPD1E10B06_0
U98 = 1A_SN74LVC1G08DCKT_SC70
Y1 = 1Y_Crystal20MHzSCM
C154 C156 C159 C161 C163 C168 C266 C333 C340 C347 C354 C361 C375 C384 C387 C395 C396 C413 C414 C483 = 1C_10uFCapacitor16V10%0805
C267 C328 C332 C351 C352 C358 C363 C365 C367 C368 C372 C377 C379 C385 C570 C572 C573 = 1C_0.01uFCapacitor16V10%0402: Cost100: 0.11; DescriptiveText: Capacitor 0.1uF 16V 10% 0402 X7R; MfrNum: C0402C104K4RACT; PN: C0402C104K4RACT; PartName: 0.1uF16V10%SMD0402; TIIntPartnumber: 1C0089
C329 C334 C338 C342 C345 C353 = 1C_0.01uFCapacitor16V10%0402: Cost100: 0.19; Cost10K: 0.045; DescriptiveText: Capacitor 0.022uF 16V 10% Ceramic 0402; MfrNum: C0402C223K4RACTU; PartName: 0.022uF,16V,10%,SMD,0402
C330 C348 C357 C362 C364 C369 C370 C373 C378 C569 C571 = 1C_0.01uFCapacitor16V10%0402: Cost100: 0.336; Cost10K: 0.201; DescriptiveText: Capacitor 1uF 10V Ceramic 10% 0402; Mfr: AVX; MfrNum: 0402ZD105KAT2A; PN: 0402ZD105KAT2A; PartName: 1uF10V10%0402; TIIntPartnumber: 1C0084
C331 C336 C337 C343 C344 C346 C355 C574 = 1C_0.01uFCapacitor16V10%0402: DescriptiveText: Capacitor 0.047uF 16V 10% 0402; MfrNum: C0402C473K4RACTU; PN: C0402C473K4RACTU; PartName: 0.047uF, 16V, 10%, SMD, 0402
C442 C445-C447 C565 C568 = 1C_1uFCapacitor10V10%0402: PN: 0402ZD105KAT2A
C473-C475 = 1C_47uFCapacitor10V10%smd2917
L21 L24-L26 L34 L35 = 1L_NFM21PC474_EMIFilter
U4 = 1A_S25FL256S_QSPI
D16-D19 D22 D23 = 1F_LED_Tricolor_RedGreenYellow: DescriptiveText: LED RedGreenBlue Tricolor 20mA 2.1/3.1/2.9V 1210 smd; MfrNum: SM1210RGB
Q1-Q6 Q10-Q16 Q20-Q25 = 1Q_MOSFET_NChan_BSS138
R239 R240 R242 R244 R249 R250 R589 R596 R601-R604 R693 R696 R699 R702 R705 R708 = 1R_150ohm1_16W1%SMD0402: DescriptiveText: Resistor 220ohm 1/10W 1% 0402; Mfr: Panasonic; MfrNum: ERJ-2RKF2200X; PartName: 220ohm1/10W1%0402; TIIntPartnumber: 1R0176
R245 R246 R251 R252 R255 R256 R280 R515 R591 R592 R595 R597 R599 R695 R697 R700 R704 R706 R709 = 1R_100KOhmResistor1_16W0402
C153 C155 C160 C162 C164 = 1C_0.1uFCapacitor16V10%0402
C157 C158 = 1C_47uFCapacitor16V20%1206
C166 C167 = 1C_0.1uFCapacitor50V10%0402
C172 C173 = 1C_18pFCapacitor16V10%0402
D3 = Diode200mA250V_0: TIIntPartnumber: _1E0013
FB1 = 1L_FerriteBead_0_1
FB2 = 1L_FerriteBead_0_3
FB3 = 1L_FerriteBead_0_2
FB4 = 1L_FerriteBead_0
J10 = 2J_ConnectorRJ45_Gigabit
Q7 = 1Q_MOSFET_PChan_FDT434P
R278 = 1R_ZeroOhmResistor1_16W0603
R279 = 1R_1.5KohmResistor1_16W5%0402
R281-R292 = 1R_22OhmResistor1_16W1%0402
R293 R296 = 1R_220ohm1_10W1%smd0402
R297 = 1R_4.7KOhmResistor1_16W0402
R298 = 1R_12.1KohmResistor1_16W1%0402
R304 R317 R319 R321 = 1R_1KOhmResistor1_16W0402
R310 R313 R315 = 1R_33ohmResistor1_16W5%0402
TP16 TP22 TP23 = 2H_Testpoint_SMD1mmCircle
U21 = 1A_KSZ9031RNX
U23 = 1A_CDCE913
Y3 = 1Y_Crystal25MHzABM3_1
C316 = 1C_1uFCapacitor50V10%0603
J21 = 2H_Header30x2_female_2mm
R113 = 1R_62OhmResistor1_16W0402
R116 = 1R_2.2KOhmResistor1_16W0402
U1 = AM571X_ABCpkg_Industrial_11
U18 = 1G_Haptics_Pico_304-100

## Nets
AGND_GBETH0: C166.2 C167.2 J10.SHLD1 J10.SHLD2
DGND: C3.2 C4.2 C5.2 C28.2 C153.2 C154.2 C155.2 C156.2 C157.2 C158.2 C159.2 C160.2 C161.2 C162.2 C163.2 C164.2 C165.2 C166.1 C167.1 C168.2 C169.2 C170.2 C171.2 C172.1 C173.1 C213.2 C214.2 C266.2 C267.2 C316.2 C327.2 C328.2 C329.2 C330.2 C331.2 C332.2 C333.2 C334.2 C335.2 C336.2 C337.2 C338.2 C339.2 C340.2 C341.2 C342.2 C343.2 C344.2 C345.2 C346.2 C347.2 C348.2 C349.2 C351.2 C352.2 C353.2 C354.2 C355.2 C356.2 C357.2 C358.2 C360.2 C361.2 C362.2 C363.2 C364.2 C365.2 C367.2 C368.2 C369.2 C370.2 C371.2 C372.2 C373.2 C374.2 C375.2 C376.2 C377.2 C378.2 C379.2 C380.2 C381.2 C384.2 C385.2 C386.2 C387.2 C388.2 C389.2 C390.2 C391.2 C393.2 C394.2 C395.2 C396.2 C413.2 C414.2 C442.2 C445.2 C446.2 C447.2 C473.2 C474.2 C475.2 C483.2 C485.2 C486.2 C487.2 C563.2 C564.2 C565.2 C566.2 C567.2 C568.2 C569.2 C570.2 C571.2 C572.2 C573.2 C574.2 C575.2 C576.2 J10.1 J10.12 J10.13 J21.22 J21.39 J21.40 J21.59 J21.60 L21.2(GND) L24.2(GND) L25.2(GND) L26.2(GND) L34.2(GND) L35.2(GND) Q1.S(SOURCE) Q2.S(SOURCE) Q3.S(SOURCE) Q4.S(SOURCE) Q5.S(SOURCE) Q6.S(SOURCE) Q10.S(SOURCE) Q11.S(SOURCE) Q12.S(SOURCE) Q13.S(SOURCE) Q14.S(SOURCE) Q15.S(SOURCE) Q16.S(SOURCE) Q20.S(SOURCE) Q21.S(SOURCE) Q22.S(SOURCE) Q23.S(SOURCE) Q24.S(SOURCE) Q25.S(SOURCE) R13.2(P2) R116.1(P1) R245.1(P1) R246.1(P1) R251.1(P1) R252.1(P1) R255.1(P1) R256.1(P1) R298.2 R304.1(P1) R317.1(P1) R319.1(P1) R321.1(P1) R515.1(P1) R569.2(P2) R591.1(P1) R592.1(P1) R595.1(P1) R597.1(P1) R599.1(P1) R695.1(P1) R697.1(P1) R700.1(P1) R704.1(P1) R706.1(P1) R709.1(P1) R793.1(P1) SW1.1 SW1.2 SW2.1 SW2.2 U1.AC14(VSSA_OSC1) U2.3(GND) U4.10(VSS) U18.M1 U18.M2 U21.13(VSS_PS) U21.29(VSS) U21.49(P_GND) U22.3(GND) U23.5(GND1) U23.10(GND2) U47.3(GND) U48.2 U49.2 U97.3(GND) U98.3(GND) ; also on sheet 1 2 3 4 5 6 7 8 9 10 11 12 14 15 16 17 18 19 20 21 22 23 24 25 26
GND_OSC0: C1.2 C2.2 R13.1(P1) U1.AF15(VSSA_OSC0)
V1_8D: C169.1 C368.1 C372.1 C373.1 C374.1 C375.1 C376.1 C377.1 C378.1 C379.1 U23.3(VDD) ; also on sheet 4 9 17 26
V1_8PHY_HDMI: C566.1 C567.1 C568.1 L35.3(OUT) ; also on sheet 17
V1_8PHY_LDO3: L25.1(IN) L34.1(IN) ; also on sheet 9
V1_8PHY_LDO4: L26.1(IN) L35.1(IN) ; also on sheet 9
V1_8PHY_PCIE: C393.1 C394.1 C447.1 L26.3(OUT) ; also on sheet 17
V1_8PHY_SATA: C563.1 C564.1 C565.1 L34.3(OUT) ; also on sheet 17
V1_8PHY_USB: C390.1 C391.1 C446.1 L25.3(OUT) ; also on sheet 17
V1_8PLL: L21.1(IN) L24.1(IN) ; also on sheet 9 17
V1_8PLLA: C380.1 C381.1 C442.1 L21.3(OUT) ; also on sheet 17
V1_8PLLB: C388.1 C389.1 C445.1 L24.3(OUT) ; also on sheet 17
V3_3D: C3.1 C28.1 C170.1 C214.1 C360.1 C361.1 C362.1 C363.1 C364.1 C365.1 C367.1 C384.1 C385.1 C386.1 C575.1 D16.1(A) D17.1(A) D18.1(A) D19.1(A) D22.1(A) D23.1(A) FB1.1 J21.1 R2.2(P2) R8.2(P2) R10.2(P2) R22.2(P2) R278.2(P2) R799.2(P2) R911.2(P2) R912.2(P2) U2.5(VCC) U4.2(VCC) U4.14(VIO/RFU) U23.6(VDDOUT1) U23.7(VDDOUT2) U47.5(VCC) U97.5(VCC) U98.5(VCC) ; also on sheet 1 2 3 4 5 6 7 8 9 10 11 12 14 15 17 18 19 20 21 22 23 24 25 26
V5_0D: J21.2 ; also on sheet 5 14 15 18 19
VDD_CORE: C339.1 C340.1 C341.1 C342.1 C343.1 C344.1 C345.1 C387.1 C473.1 C569.1 C570.1 C571.1 C572.1 C573.1 C574.1 ; also on sheet 17 19
VDD_DSP: C353.1 C354.1 C355.1 C356.1 C357.1 C358.1 C414.1 C475.1 ; also on sheet 17
VDD_GPU: C266.1 C267.1 C327.1 C328.1 C329.1 C330.1 C331.1 C396.1 ; also on sheet 17 19
VDD_IVA: C346.1 C347.1 C348.1 C349.1 C351.1 C413.1 ; also on sheet 17 19
VDD_MPU: C332.1 C333.1 C334.1 C335.1 C336.1 C337.1 C338.1 C352.1 C369.1 C370.1 C371.1 C395.1 C474.1 ; also on sheet 17 19
6PORT_LCDn: R925.2(P2) ; also on sheet 4
AM57XX_AUDIOBUZZER_TRIG: R114.1(P1) U1.A25(SPI1_SCLK)
AM57XX_GPIO6_14: R685.2(P2) U1.E21(GPIO6_14)
AM57XX_GPIO6_15: R661.2(P2) U1.F20(GPIO6_15)
AM57XX_GPIO6_16: R666.2(P2) U1.F21(GPIO6_16)
AM57XX_GPMC_AD0: R861.2(P2) U1.M6(GPMC_AD0/GPIO) ; also on sheet 10
AM57XX_GPMC_AD1: R862.2(P2) U1.M2(GPMC_AD1/GPIO) ; also on sheet 10
AM57XX_GPMC_AD2: R863.2(P2) U1.L5(GPMC_AD2/GPIO) ; also on sheet 10
AM57XX_GPMC_AD3: R864.2(P2) U1.M1(GPMC_AD3/GPIO) ; also on sheet 10
AM57XX_GPMC_AD4: R857.2(P2) U1.L6(GPMC_AD4/GPIO) ; also on sheet 10
AM57XX_GPMC_AD5: R858.2(P2) U1.L4(GPMC_AD5/GPIO) ; also on sheet 10
AM57XX_GPMC_AD6: R859.2(P2) U1.L3(GPMC_AD6/GPIO) ; also on sheet 10
AM57XX_GPMC_AD7: R860.2(P2) U1.L2(GPMC_AD7/GPIO) ; also on sheet 10
AM57XX_GPMC_AD8: R838.1(P1) U1.L1(GPMC_AD8) ; also on sheet 10
AM57XX_GPMC_AD9: R839.1(P1) U1.K2(GPMC_AD9) ; also on sheet 10
AM57XX_GPMC_AD10: R840.1(P1) U1.J1(GPMC_AD10) ; also on sheet 10
AM57XX_GPMC_AD11: R841.1(P1) U1.J2(GPMC_AD11) ; also on sheet 10
AM57XX_GPMC_AD12: R842.1(P1) U1.H1(GPMC_AD12) ; also on sheet 10
AM57XX_GPMC_AD13: R843.1(P1) U1.J3(GPMC_AD13) ; also on sheet 10
AM57XX_GPMC_AD14: R844.1(P1) U1.H2(GPMC_AD14) ; also on sheet 10
AM57XX_GPMC_AD15: R845.1(P1) U1.H3(GPMC_AD15) ; also on sheet 10
AM57XX_INDETHER_LED0_GRN: R247.1(P1) R803.2(P2)
AM57XX_INDETHER_LED0_RED: R241.2(P2) U1.B26(XREF_CLK2)
AM57XX_INDETHER_LED0_YEL: R253.1(P1) U1.D15(MCASP2_AXR4)
AM57XX_INDETHER_LED1_GRN: R248.1(P1) U1.B17(MCASP2_AXR6)
AM57XX_INDETHER_LED1_RED: R243.2(P2) U1.B16(MCASP2_AXR5)
AM57XX_INDETHER_LED1_YEL: R254.1(P1) U1.A17(MCASP2_AXR7)
AM57XX_INDETHER_LED2_GRN: R590.1(P1) U1.F16(SPI1_D1)
AM57XX_INDETHER_LED2_RED: R600.2(P2) U1.B25(SPI1_D0)
AM57XX_INDETHER_LED2_YEL: R594.1(P1) U1.A24(SPI1_CS0)
AM57XX_INDETHER_LED3_GRN: R593.1(P1) U1.C27(UART1_RTS/GPIO7_25)
AM57XX_INDETHER_LED3_RED: R514.2(P2) U1.A22(SPI1_CS1)
AM57XX_INDETHER_LED3_YEL: R598.1(P1) U1.E25(UART1_CTS/GPIO7_24)
AM57XX_MCASP1_AXR4: R673.2(P2) U1.E12(MCASP1_AXR4)
AM57XX_MCASP1_AXR6: R675.2(P2) U1.C12(MCASP1_AXR6)
AM57XX_MCASP1_AXR7: R676.2(P2) U1.D12(MCASP1_AXR7)
AM57XX_OSC0_IN: C2.1 R4.2(P2) U1.AE15(XI_OSC0) Y1.3
AM57XX_OSC0_OUT: R5.1(P1) U1.AD15(XO_OSC0)
AM57XX_PORZn: R6.2(P2) U1.F22(PORZ)
AM57XX_PR1_UART0_RXD: R851.1(P1) ; also on sheet 12
AM57XX_PR1_UART0_TXD: R852.1(P1) ; also on sheet 12 24
AM57XX_PR2_PROFI_TXEN: J21.49 ; also on sheet 12
AM57XX_PRU2ETH0_COL: R930.1(P1) ; also on sheet 24
AM57XX_PRU2ETH0_CRS: R929.1(P1) ; also on sheet 24
AM57XX_PRU2ETH1_COL: R893.1(P1) ; also on sheet 21
AM57XX_PRU2ETH1_CRS: R892.1(P1) ; also on sheet 21
AM57XX_RSTOUTn: R36.2(P2) R916.1(P1) U1.F23(RSTOUTn) U47.2(A)
AM57XX_SPI2_CS0: R890.1(P1) U1.B24(SPI2_CS0)
AM57XX_SPI2_DIN: R888.1(P1) U1.G17(SPI2_D0)
AM57XX_SPI2_DOUT: R889.1(P1) U1.B22(SPI2_D1)
AM57XX_SPI2_SCLK: R684.1(P1) U1.A26(SPI2_SCLK)
AM57XX_STATUSLED0_GRN: R701.1(P1) R732.1(P1) U1.N6(GPMC_BEN0)
AM57XX_STATUSLED0_RED: R692.1(P1) R698.2(P2) U1.M3(GPMC_WEN)
AM57XX_STATUSLED0_YEL: R694.1(P1) R733.1(P1) U1.M4(GPMC_BEN1)
AM57XX_STATUSLED1_GRN: R688.1(P1) R710.1(P1) U1.P1(GPMC_CS3/GPIO)
AM57XX_STATUSLED1_RED: R707.2(P2) R734.1(P1) U1.N2(GPMC_WAIT0)
AM57XX_STATUSLED1_YEL: R686.1(P1) R703.1(P1) U1.T1(GPMC_CS0)
AM57XX_UART3_RXD: U1.D27(UART2_CTS/UART3_RXD) ; also on sheet 1
AM57XX_UART3_TXD: U1.C28(UART2_RTS/UART3_TXD) ; also on sheet 1
AM57XX_VIN2A_DE0: R670.1(P1) R847.1(P1) U1.G2(VIN2A_DE0) ; also on sheet 21
AM57XX_VIN2A_HSYNC0: R672.1(P1) R849.1(P1) U1.G1(VIN2A_HSYNC0) ; also on sheet 21
AM571X_PRU1ETH1_COL: R743.2(P2) ; also on sheet 22
AM571X_PRU1ETH1_TXD0: R856.1(P1) ; also on sheet 12 22
AM571X_PRU1ETH1_TXD1: R855.1(P1) ; also on sheet 22
AM571X_RGMII0_RD0: R289.2(P2) U1.W2(RGMII0_RXD0)
AM571X_RGMII0_RD1: R290.2(P2) U1.Y2(RGMII0_RXD1)
AM571X_RGMII0_RD2: R291.2(P2) U1.V3(RGMII0_RXD2)
AM571X_RGMII0_RD3: R292.2(P2) U1.V4(RGMII0_RXD3)
AM571X_RGMII0_RXCLK: R288.2(P2) R887.1(P1) U1.U5(RGMII0_RXC)
AM571X_RGMII0_RXCTL: R285.2(P2) U1.V5(RGMII0_RXCTL)
AM571X_RGMII0_TD0: R282.2(P2) R883.1(P1) U1.U6(RGMII0_TXD0)
AM571X_RGMII0_TD1: R287.2(P2) R884.1(P1) U1.V6(RGMII0_TXD1)
AM571X_RGMII0_TD2: R283.2(P2) R885.1(P1) U1.U7(RGMII0_TXD2)
AM571X_RGMII0_TD3: R284.2(P2) R886.1(P1) U1.V7(RGMII0_TXD3)
AM571X_RGMII0_TXCLK: R281.2(P2) R881.1(P1) U1.W9(RGMII0_TXC)
AM571X_RGMII0_TXCTL: R286.2(P2) R882.1(P1) U1.V9(RGMII0_TXCTL)
AM571X_VIN2A_CLK0: R669.1(P1) R846.1(P1) U1.E1(VIN2A_CLK0)
AM571X_VIN2A_D2: R853.1(P1) ; also on sheet 4
AM571X_VIN2A_FLD0: R671.1(P1) R848.1(P1) U1.H7(VIN2A_FLD0)
AM571X_VIN2A_VSYNC0: R803.1(P1) R850.1(P1) U1.G6(VIN2A_VSYNC0) ; also on sheet 24
AM571X_VOUT1_FLD: R564.1(P1) U1.B11(VOUT1_FLD)
AM572X_QSPI_CLK: R24.2(P2) U1.R2(GPMC_A18/QSPI1_SCLK)
AM572X_QSPI_CSn: R30.2(P2) U1.P2(GPMC_CS2/QSPI1_CS0)
AM572X_QSPI_D0: R25.2(P2) U1.U1(GPMC_A16/QSPI1_D0)
AM572X_QSPI_D1: R26.2(P2) U1.P3(GPMC_A17/QSPI1_D1)
AM572X_QSPI_D2: R27.2(P2) U1.U2(GPMC_A15/QSPI_D2)
AM572X_QSPI_D3: R28.2(P2) U1.T2(GPMC_A14/QSPI_D3)
AM572X_QSPI_RTCLK: R23.2(P2) U1.R3(GPMC_A13/QSPI_RTCLK)
CAM_ENn: R685.1(P1) ; also on sheet 11
CAN1_RXDF: J21.41 ; also on sheet 6
CAN1_TXDF: J21.43 ; also on sheet 6
eMMC_RSTn: R564.2(P2) ; also on sheet 2
ETH0_LDO_O: Q7.G(GATE) U21.43(LDO_O)
ETH0_MDC: R294.1(P1) U21.36(MDC)
ETH0_MDIO: R295.1(P1) U21.37(MDIO)
ETH0_RXCLK: R288.1(P1) R317.2(P2) U21.35(RX_CLK)
ETH0_RXD0: R289.1(P1) R299.2(P2) U21.32(RXD0)
ETH0_RXD1: R290.1(P1) R301.2(P2) U21.31(RXD1)
ETH0_RXD2: R291.1(P1) R306.2(P2) U21.28(RXD2)
ETH0_RXD3: R292.1(P1) R309.2(P2) U21.27(RXD3)
ETH0_RXDV: R285.1(P1) R304.2(P2) U21.33(RX_DV)
ETH0_TXCLK: R281.1(P1) U21.24(GTX_CLK)
ETH0_TXD0: R282.1(P1) U21.19(TXD0)
ETH0_TXD1: R287.1(P1) U21.20(TXD1)
ETH0_TXD2: R283.1(P1) U21.21(TXD2)
ETH0_TXD3: R284.1(P1) U21.22(TXD3)
ETH0_TXEN: R286.1(P1) U21.25(TX_EN)
ETH0GB_25MHzCLK: R315.2 U21.46(XI)
ETH_MDIO_CLK: R294.2(P2) R877.1(P1) U1.V1(MDIO_MCLK) ; also on sheet 26
ETH_MDIO_DATA: R279.1(P1) R295.2(P2) R878.1(P1) U1.U4(MDIO_D) ; also on sheet 26
ETHER0_D0N: J10.10 U21.3(TXRXM_A)
ETHER0_D0P: J10.9 U21.2(TXRXP_A)
ETHER0_D1N: J10.8 U21.6(TXRXM_B)
ETHER0_D1P: J10.7 U21.5(TXRXP_B)
ETHER0_D2N: J10.6 U21.8(TXRXM_C)
ETHER0_D2P: J10.5 U21.7(TXRXP_C)
ETHER0_D3N: J10.4 U21.11(TXRXM_D)
ETHER0_D3P: J10.3 U21.10(TXRXP_D)
GB_ETH0_INTn: R297.1(P1) R662.1(P1) U21.38(INT_N_/_PME_N2)
GB_ETH1_INTn: R663.1(P1) ; also on sheet 26
GBETH0_RESETn: C168.1 D3.2 R280.1(P1) U21.42(RESET_N) U22.4(Y)
GPIO_IND_LDn: R690.1(P1) U1.N1(GPMC_ADVN_ALE) ; also on sheet 18
GPIO_PCIE_RSTDRVn: R659.1(P1) ; also on sheet 20
GPIO_PCIE_SWRSTn: R660.1(P1) ; also on sheet 20
GPIO_PRU1_ETH_RESETn: R675.1(P1) ; also on sheet 22 23
GPIO_PRU2_ETH_RESETn: R676.1(P1) ; also on sheet 21 24
GPIO_TOUCH_RESETn: R661.1(P1) ; also on sheet 4
GPIO_USB2_VBUS_DET: R904.2(P2) ; also on sheet 9
GPIO_VPP_PWR_EN: R691.1(P1) U1.M5(GPMC_OEN_REN) ; also on sheet 17
HAPTICS_N: Q16.D(DRAIN) U18.2(N-)
HAPTICS_P: C316.1 R113.1(P1) U18.1(P+)
HDQ: R891.1(P1) ; also on sheet 11
IND_I2C_SCL: J21.27 R314.2(P2) ; also on sheet 4 9 10 11 18 20
IND_I2C_SDA: J21.29 R312.2(P2) ; also on sheet 4 9 10 11 18 20
OSC0_OUT: C1.1 R4.1(P1) R5.2(P2) Y1.1
PCIE_CRDPRESENT: R664.1(P1) ; also on sheet 20
PCIE_RESETn: R917.2(P2) R918.2(P2) ; also on sheet 20
PCIE_WAKEn: R665.1(P1) ; also on sheet 20
PHY0_LED_ACTn: R293.1 R321.2(P2) U21.17(LED1_/_PME_N1)
PHY0_LED_LINKn: R296.1 R319.2(P2) U21.15(LED2)
PHY_RESETn: R913.2(P2) R914.2(P2) U22.2(A) ; also on sheet 21 22 23 24 26
PMIC_INT: R666.1(P1) ; also on sheet 9
PMIC_RESET_OUTn: R9.1(P1) ; also on sheet 9
PORZn: C213.1 R6.1(P1) R914.1(P1) R918.1(P1) U98.4(Y) ; also on sheet 3
PR1_MII0_COL: R876.1(P1) ; also on sheet 4 23
PR1_MII0_RXD0: R873.2(P2) ; also on sheet 4 23
PR1_MII0_RXD1: R872.2(P2) ; also on sheet 4 23
PR1_MII0_RXD2: R871.2(P2) ; also on sheet 4 23
PR1_MII0_RXD3: R870.2(P2) ; also on sheet 4 23
PR1_MII0_RXDV: R869.2(P2) ; also on sheet 4 23
PR1_MII0_RXER: R874.1(P1) ; also on sheet 4 23
PR1_MII0_RXLINK: R875.1(P1) ; also on sheet 4 23
PR1_MII0_TXD0: R867.2(P2) ; also on sheet 4 23
PR1_MII0_TXD1: R866.2(P2) ; also on sheet 4 23
PR1_MII0_TXD2: R753.2(P2) ; also on sheet 4 23
PR1_MII0_TXD3: R752.2(P2) ; also on sheet 4 23
PR1_MII0_TXEN: R865.2(P2) ; also on sheet 4 23
PR1_MII1_CRS: R744.2(P2) ; also on sheet 4 22
PR1_MII1_MR1_CLK: R745.2(P2) ; also on sheet 4 22
PR1_MII1_RXD0: R750.2(P2) ; also on sheet 4 22
PR1_MII1_RXD1: R749.2(P2) ; also on sheet 4 22
PR1_MII1_RXD2: R748.2(P2) ; also on sheet 4 22
PR1_MII1_RXD3: R747.2(P2) ; also on sheet 4 22
PR1_MII1_RXDV: R746.2(P2) ; also on sheet 4 22
PR1_MII_MR0_CLK: R868.2(P2) ; also on sheet 4 23
PR1_MII_MT0_CLK: R751.2(P2) ; also on sheet 4 23
PRU1ETH0_25MHzCLK: R310.2 ; also on sheet 23
PRU1ETH0_INTn: R669.2(P2) ; also on sheet 23
PRU1ETH1_25MHzCLK: R313.2 ; also on sheet 22
PRU1ETH1_INTn: R670.2(P2) ; also on sheet 22
PRU2ETH0_INTn: R671.2(P2) ; also on sheet 24
PRU2ETH1_INTn: R672.2(P2) ; also on sheet 21
QSPI_CLK: R23.1(P1) R24.1(P1) R31.2(P2)
RSTOUTTOPMIC: R36.1(P1) R793.2(P2) ; also on sheet 9
SPIMEM_CLK: R31.1(P1) U4.16(SCK)
SPIMEM_CSn: R30.1(P1) U4.7(~{CS})
SPIMEM_D0: R25.1(P1) U4.15(SI/IO0)
SPIMEM_D1: R26.1(P1) U4.8(SO/IO1)
SPIMEM_D2: R22.1(P1) R27.1(P1) U4.9(~{WP}/IO2)
SPIMEM_D3: R28.1(P1) R799.1(P1) U4.1(~{HOLD}/IO3)
SYS_RESETn: J21.25 R29.2(P2) R915.2(P2) R916.2(P2) ; also on sheet 4
SYS_WARMRESETn: C576.1 R2.1(P1) R7.2(P2) R913.1(P1) R915.1(P1) R917.1(P1) U47.4(Y) U97.4(Y) ; also on sheet 1 10
TOUCH_INT: R673.1(P1) ; also on sheet 4
UART1_RXD: R879.1(P1) R904.1(P1) U1.B27(UART1_RXD/GPIO7_22)
UART1_TXD: R880.1(P1) U1.C26(UART1_TXD/GPIO7_23)
VETH0_AVDDH: C153.1 C154.1 C157.1 FB1.2 Q7.S(SOURCE) U21.1(AVDDH) U21.12(AVDDH) U21.47(AVDDH)
VETH0_AVDDL: C161.1 C162.1 FB4.2 U21.4(AVDDL) U21.9(AVDDL)
VETH0_AVDDL_PLL: C163.1 C164.1 C165.1 FB2.2 U21.44(AVDDL_PLL)
VETH0_AVDDL_PMOS: C158.1 FB2.1 FB3.1 FB4.1 Q7.D1(DRAIN1) Q7.D2(DRAIN2)
VETH0_DVDDH: C155.1 C156.1 C171.1 D3.1 R278.1(P1) R279.2(P2) R280.2(P2) R297.2(P2) R299.1(P1) R301.1(P1) R306.1(P1) R309.1(P1) U21.16(DVDDH) U21.34(DVDDH) U21.40(DVDDH) U22.5(VCC)
VETH0_DVDDL: C159.1 C160.1 FB3.2 U21.14(DVDDL) U21.18(DVDDL) U21.23(DVDDL) U21.26(DVDDL) U21.30(DVDDL) U21.39(DVDDL)
VMAIN: R113.2(P2) ; also on sheet 4 9 11 19
VSDMMC: C483.1 C485.1 C486.1 C487.1 ; also on sheet 9 17 25
N10692191: R11.2(P2) SW2.3 SW2.4 U48.1
N12123192: J10.11 R293.2
N12123204: J10.14 R296.2
N12138943: R298.1 U21.48(ISET)
N12139138: TP16.1 U21.41(CLK125_NDO)
N16383240: C5.1 R11.1(P1) R911.1(P1) U97.2(A)
N17120040: J21.3 R743.1(P1)
N17120055: J21.5 R744.1(P1)
N17120058: J21.7 R745.1(P1)
N17120061: J21.9 R746.1(P1)
N17120072: J21.11 R747.1(P1)
N17120075: J21.13 R748.1(P1)
N17120078: J21.15 R749.1(P1)
N17120081: J21.17 R750.1(P1)
N17120084: J21.19 R751.1(P1)
N17120087: J21.21 R752.1(P1)
N17120090: J21.23 R753.1(P1)
N17120397: J21.45 R869.1(P1)
N17120400: J21.47 R870.1(P1)
N17120403: J21.24 R684.2(P2) R883.2(P2)
N17144335: R29.1(P1) U4.3(~{RESET})
N17156111: C172.2 R305.2(P2) U23.1(Xin/CLK) Y3.2
N17156113: C173.2 R305.1(P1) R308.2(P2) Y3.1
N17156222: R308.1(P1) U23.14(XOUT)
N17156522: R310.1 U23.11(Y1)
N17156525: R313.1 U23.9(Y2)
N17156528: R315.1 U23.8(Y3)
N17156983: R314.1(P1) U23.12(S2/SCL)
N17156986: R312.1(P1) U23.13(S1/SDA)
N17731118: Q1.G(GATE) R241.1(P1) R245.2(P2)
N17731139: Q5.G(GATE) R253.2(P2) R255.2(P2)
N19425975: R7.1(P1) U1.E23(RESETn)
N19426030: R8.1(P1) U1.D21(NMI_DSP)
N19426454: R569.1(P1) U1.AC15(XI_OSC1)
N20631200: Q16.G(GATE) R114.2(P2) R116.2(P2)
N20721609: Q3.G(GATE) R247.2(P2) R251.2(P2)
N20721766: Q3.D(DRAIN) R242.1(P1)
N20721850: Q1.D(DRAIN) R239.1(P1)
N20722196: D16.3(G) R242.2(P2)
N20722199: Q5.D(DRAIN) R249.1(P1)
N20722204: D16.4(Y) R249.2(P2)
N20722213: D16.2(R) R239.2(P2)
N20722605: Q2.G(GATE) R243.1(P1) R246.2(P2)
N20722618: Q6.G(GATE) R254.2(P2) R256.2(P2)
N20722739: Q4.G(GATE) R248.2(P2) R252.2(P2)
N20722773: Q4.D(DRAIN) R244.1(P1)
N20722790: Q2.D(DRAIN) R240.1(P1)
N20722809: D17.3(G) R244.2(P2)
N20722811: Q6.D(DRAIN) R250.1(P1)
N20722815: D17.4(Y) R250.2(P2)
N20722821: D17.2(R) R240.2(P2)
N20723137: Q11.G(GATE) R599.2(P2) R600.1(P1)
N20723150: Q10.G(GATE) R594.2(P2) R595.2(P2)
N20723271: Q15.G(GATE) R590.2(P2) R591.2(P2)
N20723305: Q15.D(DRAIN) R589.1(P1)
N20723322: Q11.D(DRAIN) R596.1(P1)
N20723341: D18.3(G) R589.2(P2)
N20723343: Q10.D(DRAIN) R601.1(P1)
N20723347: D18.4(Y) R601.2(P2)
N20723353: D18.2(R) R596.2(P2)
N20723697: Q13.G(GATE) R514.1(P1) R597.2(P2)
N20723710: Q12.G(GATE) R515.2(P2) R598.2(P2)
N20723831: Q14.G(GATE) R592.2(P2) R593.2(P2)
N20723865: Q14.D(DRAIN) R603.1(P1)
N20723882: Q13.D(DRAIN) R604.1(P1)
N20723901: D19.3(G) R603.2(P2)
N20723903: Q12.D(DRAIN) R602.1(P1)
N20723907: D19.4(Y) R602.2(P2)
N20723913: D19.2(R) R604.2(P2)
N20729664: Q20.D(DRAIN) R699.1(P1)
N20729666: D22.4(Y) R699.2(P2)
N20729672: D22.2(R) R696.2(P2)
N20729903: Q21.G(GATE) R697.2(P2) R698.1(P1)
N20729915: Q20.G(GATE) R694.2(P2) R695.2(P2)
N20730029: Q22.G(GATE) R700.2(P2) R701.2(P2)
N20730054: Q22.D(DRAIN) R693.1(P1)
N20730079: Q21.D(DRAIN) R696.1(P1)
N20730095: D22.3(G) R693.2(P2)
N20730773: Q23.D(DRAIN) R708.1(P1)
N20730775: D23.4(Y) R708.2(P2)
N20730781: D23.2(R) R705.2(P2)
N20730789: Q24.G(GATE) R706.2(P2) R707.1(P1)
N20730805: Q23.G(GATE) R703.2(P2) R704.2(P2)
N20730910: Q25.G(GATE) R709.2(P2) R710.2(P2)
N20730936: Q25.D(DRAIN) R702.1(P1)
N20730961: Q24.D(DRAIN) R705.1(P1)
N20730985: D23.3(G) R702.2(P2)
N21013400: R662.2(P2) U1.B14(MCASP1_ACLKR)
N21013403: R663.2(P2) U1.J14(MCASP1_FSR)
N21013406: R664.2(P2) U1.G13(MCASP1_AXR2)
N21013409: R665.2(P2) U1.J11(MCASP1_AXR3)
N21036262: J21.4 R686.2(P2) R877.2(P2)
N21036269: J21.6 R688.2(P2) R878.2(P2)
N21036279: J21.8 R690.2(P2) R880.2(P2)
N21036281: J21.10 R691.2(P2) R879.2(P2)
N21036293: J21.12 R692.2(P2) R874.2(P2)
N21036295: J21.14 R732.2(P2) R875.2(P2)
N21036304: J21.16 R733.2(P2) R876.2(P2)
N21036311: J21.58 R689.2(P2)
N21036394: R689.1(P1) R925.1(P1) U1.P7(GPMC_CLK)
N21036619: J21.52 R734.2(P2)
N21180149: TP22.1 U1.B15(MCASP2_AXR0)
N21180152: TP23.1 U1.A15(MCASP2_AXR1)
N22242148: R660.2(P2) U1.V2(UART3_RXD/GPIO5_18)
N22242162: R659.2(P2) U1.Y1(UART3_TXD/GPIO5_19)
N22817064: J21.32 R838.2(P2) R846.2(P2)
N22817067: J21.34 R839.2(P2) R847.2(P2)
N22817070: J21.36 R840.2(P2) R848.2(P2)
N22817073: J21.38 R841.2(P2) R849.2(P2)
N22817076: J21.42 R842.2(P2) R850.2(P2)
N22817095: J21.44 R843.2(P2) R851.2(P2)
N22817104: J21.46 R844.2(P2) R852.2(P2)
N22817113: J21.48 R845.2(P2) R853.2(P2)
N22843188: J21.54 R855.2(P2) R929.2(P2)
N22843197: J21.56 R856.2(P2) R930.2(P2)
N22941894: J21.51 R857.1(P1) R871.1(P1)
N22941897: J21.53 R858.1(P1) R872.1(P1)
N22941900: J21.55 R859.1(P1) R873.1(P1)
N22942582: J21.31 R861.1(P1) R865.1(P1)
N22942589: J21.33 R862.1(P1) R866.1(P1)
N22942599: J21.35 R863.1(P1) R867.1(P1)
N22942601: J21.37 R864.1(P1) R868.1(P1)
N22982995: J21.26 R884.2(P2) R888.2(P2)
N22983025: J21.28 R885.2(P2) R889.2(P2)
N22983056: J21.30 R886.2(P2) R890.2(P2)
N22983147: J21.50 R887.2(P2) R891.2(P2)
N22983150: J21.18 R881.2(P2) R892.2(P2)
N22983153: J21.20 R882.2(P2) R893.2(P2)
N23074888: J21.57 R860.1(P1)
N23403418: C4.1 R10.1(P1) R12.1(P1) U2.2(A)
N23403425: R12.2(P2) SW1.3 SW1.4 U49.1
N23403875: R9.2(P2) U98.1(A)
N23404270: R912.1(P1) U2.4(Y) U98.2(B)

Not connected (* = marked no-connect by the designer): J10 2; U1 A20(MCASP2_FSR) AA1(MLBP_DAT_P) AA2(MLBP_DAT_N) AA4(MCASP5_AXR1) AB1(MLBP_CLK_P) AB2(MLBP_CLK_N) AB3(MCASP5_AXR0) AC1(MLBP_SIG_P) AC2(MLBP_SIG_N) AC13(XO_OSC1) AD2(CSI2_0_DY0) AD3(NC) AD8(NC) AD9(NC) AE1(CSI2_0_DX0) AE2(CSI2_0_DY1) AE3(NC) AE5(NC) AE6(NC) AE8(NC) AE9(NC) AF1(CSI2_0_DX1) AF2(CSI2_0_DX2) AF3(CSI2_0_DY2) AF4(NC) AF6(NC) AF8(NC) AF9(NC) AG2(NC) AG3(CSI2_0_DY4) AG4(CSI2_0_DY3) AG5(CSI2_1_DX0) AG6(CSI2_1_DX1) AG7(CSI2_1_DY2) AG8(NC) AG9(SATA1_RXP0) AG10(SATA1_TXN0) AG11(NC) AG12(NC) AH3(CSI2_0_DX4) AH4(CSI2_0_DX3) AH5(CSI2_1_DY0) AH6(CSI2_1_DY1) AH7(CSI2_1_DX2) AH9(SATA1_RXN0) AH10(SATA1_TXP0) AH11(NC) AH12(NC) E15(MCASP2_ACLKR) E26(NC) E27(NC) E28(NC) F24(NC) F25(NC) F26(NC) F27(NC) F28(NC) G16(MCASP4_AXR0) G24(NC) G25(NC) G26(NC) G27(NC) G28(NC) H23(NC) H24(NC) H25(NC) H26(NC) H27(NC) H28(NC) J20(NC) J23(NC) J24(NC) J25(NC) J26(NC) K20(NC) K21(NC) K22(NC) K23(NC) K27(NC) K28(NC) L22(NC) L23(NC) L24(NC) L25(NC) L26(NC) L27(NC) L28(NC) M22(NC) M23(NC) M24(NC) M25(NC) M26(NC) M27(NC) M28(NC) N20(NC) N22(NC) N23(NC) N27(NC) N28(NC) P22(NC) P23(NC) P24(NC) P25(NC) P26(NC) P27(NC) R22(NC) R23(NC) R24(NC) R25(NC) R26(NC) R27(NC) R28(NC) T22(NC) T23(NC) T27(NC) T28(NC) U22(NC) U23(NC) U24(NC) U25(NC) U26(NC) U27(NC) U28(NC); U2 1(NC)*; U4 4(NC4)* 5(NC5)* 6(NC6)* 11(NC11)* 12(NC12)* 13(NC13)*; U21 45(XO)*; U22 1(NC)*; U23 2(S0)* 4(Vctr)*; U47 1(NC)*; U97 1(NC)*; Y1 2(NC0)* 4(NC1)*

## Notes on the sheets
sheet 29
- Expansion Connector
- PR1_EDC_LATCH0
- PR2_EDC_LATCH0
- PR2_EDC_LATCH1
- PR2_EDC_SYNC0
- PR2_EDC_LATCH0 (ES2.0)
- PR2_EDC_SYNC1
- PR1_EDC_LATCH0 (ES2.0)
- PR1_EDC_SYNC0
- AM571X_VIN2A_D5
- PR1_EDC_SYNC0 (ES2.0)
- PR2_EDC_SYNC0 (ES2.0)
- PR2_UART0_RXD
- PR2_UART0_TXD
- AM571X_VIN2A_D0
- AM571X_VIN2A_D1
- AM571X_VIN2A_D2
sheet 30
- User Warm Reset Switch
sheet 32
- Industrial Ethernet LED's
- Status LED's
